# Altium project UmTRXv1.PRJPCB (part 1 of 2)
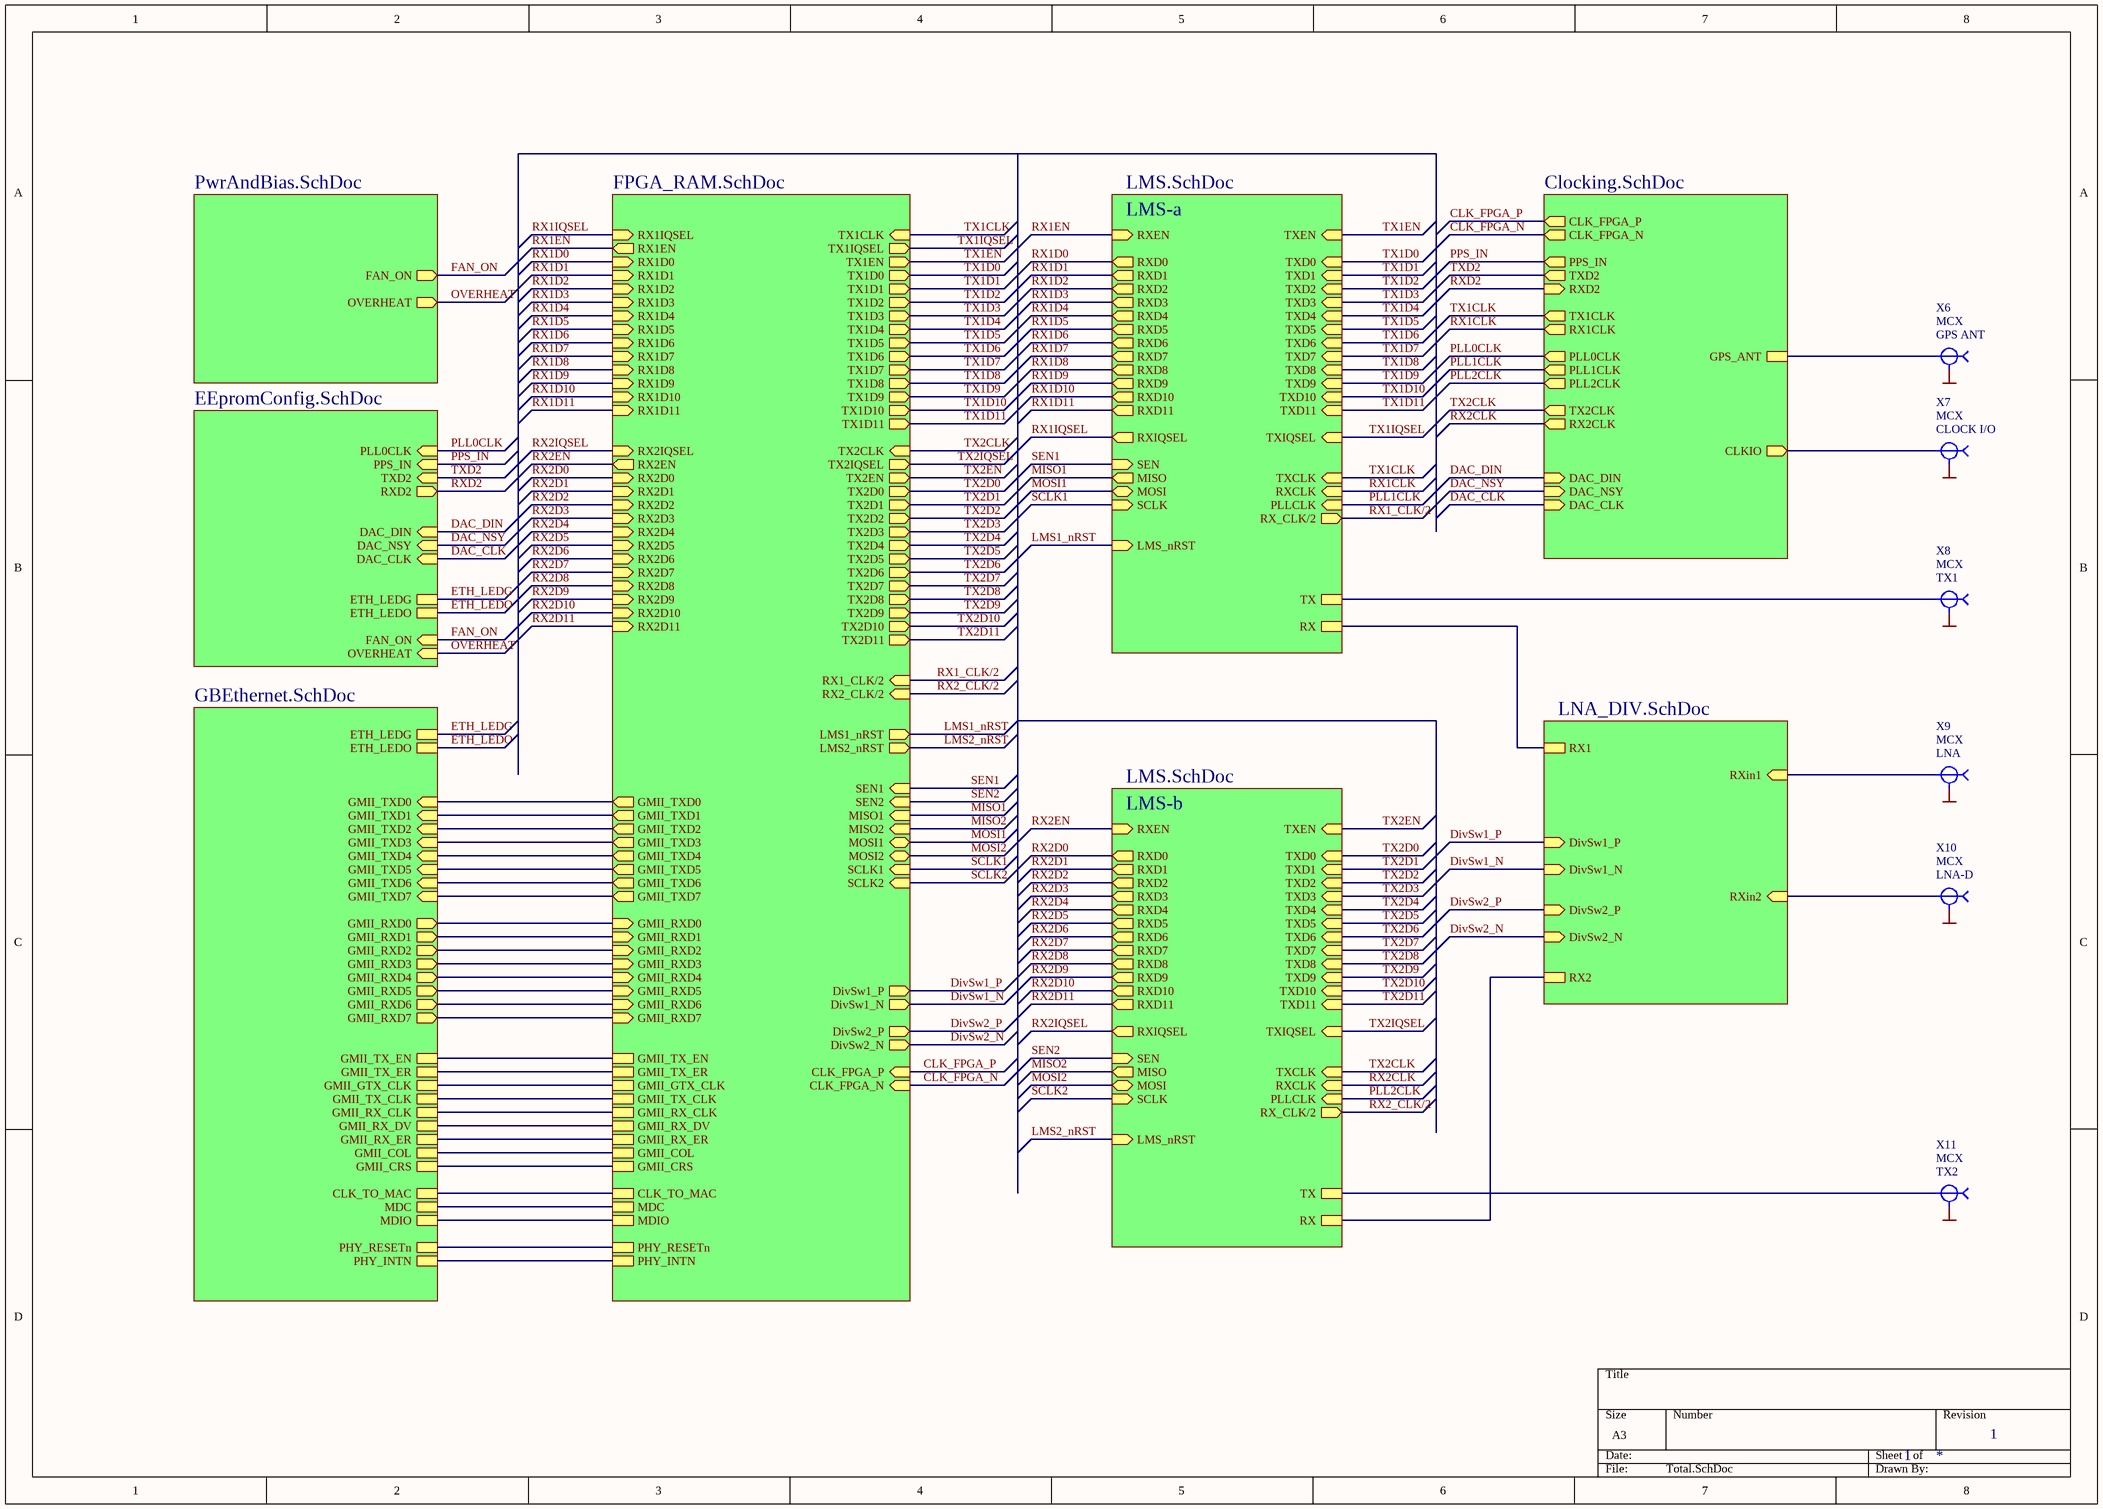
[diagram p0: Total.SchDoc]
8 sheets, 766 parts. Net scope: hierarchical (ports join the sheet entries above them; power ports are global).
Board file: UmTRXv1.PcbDoc
Sheets:
  Total.SchDoc
    PwrAndBias = PwrAndBias.SchDoc
    FPGA_RAM = FPGA_RAM.SchDoc
    GBEthernet = GBEthernet.SchDoc
    EEpromConfig = EEpromConfig.SchDoc
    Clocking = Clocking.SchDoc
    LMS-a = LMS.SchDoc
    LNA_DIV = LNA_DIV.SchDoc
    LMS-b = LMS.SchDoc

## Sheet Total.SchDoc: USRP Cellular Tranceiver
size A3; Revision: 1; SheetNumber: 1

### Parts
X6  MCX  Dscription: GPS ANT  [RF-MCX]
X7  MCX  Dscription: CLOCK I/O  [RF-MCX]
X8  MCX  Dscription: TX1  [RF-MCX]
X9  MCX  Dscription: LNA  [RF-MCX]
X10  MCX  Dscription: LNA-D  [RF-MCX]
X11  MCX  Dscription: TX2  [RF-MCX]

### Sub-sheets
Clocking = Clocking.SchDoc: RXD2 (in), RX2CLK (out), TX2CLK (out), CLKIO (out), CLK_FPGA_P (out), CLK_FPGA_N (out), RX1CLK (out), PLL1CLK (out), TX1CLK (out), GPS_ANT, DAC_DIN (in), DAC_NSY (in), DAC_CLK (in), PPS_IN (out), TXD2 (out), PLL2CLK (out), PLL0CLK (out)
EEpromConfig = EEpromConfig.SchDoc: PPS_IN (in), DAC_DIN (in), DAC_NSY (in), DAC_CLK (in), RXD2 (out), TXD2 (in), ETH_LEDG, ETH_LEDO, PLL0CLK (in), FAN_ON (in), OVERHEAT (in)
FPGA_RAM = FPGA_RAM.SchDoc: DivSw1_P (out), DivSw1_N (out), TX1IQSEL (out), TX2IQSEL (out), RX1IQSEL (in), RX2IQSEL (in), SEN1 (in), SEN2 (in), MISO1 (in), MOSI1 (bidir), SCLK1 (in), RX1EN (out), TX1EN (out), DivSw2_P (out), DivSw2_N (out), CLK_FPGA_P (in), CLK_FPGA_N (in), CLK_TO_MAC, GMII_TX_EN, GMII_TX_ER, GMII_GTX_CLK, GMII_TX_CLK, GMII_RX_CLK, GMII_RX_DV, GMII_RX_ER, GMII_COL, GMII_CRS, MDIO, MDC, PHY_INTN, PHY_RESETn, MISO2 (in), MOSI2 (bidir), SCLK2 (in), LMS1_nRST (out), RX1_CLK/2 (in), RX2_CLK/2 (in), TX2EN (out), RX2EN (out), LMS2_nRST (out), TX2CLK (in), TX1CLK (in), TX1D0 (out), TX1D1 (out), TX1D2 (out), TX1D3 (out), TX1D4 (out), TX1D5 (out), TX1D6 (out), TX1D7 (out), TX1D8 (out), TX1D9 (out), TX1D10 (out), TX1D11 (out), TX2D0 (out), TX2D1 (out), TX2D2 (out), TX2D3 (out), TX2D4 (out), TX2D5 (out), TX2D6 (out), TX2D7 (out), TX2D8 (out), TX2D9 (out), TX2D10 (out), TX2D11 (out), RX1D0 (in), RX1D1 (in), RX1D2 (in), RX1D3 (in), RX1D4 (in), RX1D5 (in), RX1D6 (in), RX1D7 (in), RX1D8 (in), RX1D9 (in), RX1D10 (in), RX1D11 (in), RX2D0 (in), RX2D1 (in), RX2D2 (in), RX2D3 (in), RX2D4 (in), RX2D5 (in), RX2D6 (in), RX2D7 (in), RX2D8 (in), RX2D9 (in), RX2D10 (in), RX2D11 (in), GMII_TXD0 (out), GMII_TXD1 (out), GMII_TXD2 (out), GMII_TXD3 (out), GMII_TXD4 (out), GMII_TXD5 (out), GMII_TXD6 (out), GMII_TXD7 (out), GMII_RXD0 (in), GMII_RXD1 (in), GMII_RXD2 (in), GMII_RXD3 (in), GMII_RXD4 (in), GMII_RXD5 (in), GMII_RXD6 (in), GMII_RXD7 (in)
GBEthernet = GBEthernet.SchDoc: CLK_TO_MAC, GMII_TX_ER, GMII_TX_EN, GMII_GTX_CLK, GMII_RX_CLK, GMII_TX_CLK, GMII_RX_DV, GMII_RX_ER, GMII_COL, GMII_CRS, MDC, MDIO, PHY_INTN, PHY_RESETn, ETH_LEDG, GMII_TXD0 (in), GMII_TXD1 (in), GMII_TXD2 (in), GMII_TXD3 (in), GMII_TXD4 (in), GMII_TXD5 (in), GMII_TXD6 (in), GMII_TXD7 (in), GMII_RXD0 (out), GMII_RXD1 (out), GMII_RXD2 (out), GMII_RXD3 (out), GMII_RXD4 (out), GMII_RXD5 (out), GMII_RXD6 (out), GMII_RXD7 (out), ETH_LEDO
LMS-a = LMS.SchDoc: RXD0 (out), RXIQSEL (out), SEN (in), MISO (out), MOSI (bidir), SCLK (in), RXD1 (out), RXD2 (out), RXD3 (out), RXD4 (out), RXD5 (out), RXD6 (out), RXD7 (out), RXD8 (out), RXD9 (out), RXD10 (out), RXD11 (out), RXEN (in), TXD0 (in), TXIQSEL (in), PLLCLK (in), RXCLK (in), TXCLK (in), TXD1 (in), TXD2 (in), TXD3 (in), TXD4 (in), TXD5 (in), TXD6 (in), TXD7 (in), TXD8 (in), TXD9 (in), TXD10 (in), TXD11 (in), TXEN (in), TX, RX, LMS_nRST (in), RX_CLK/2 (out)
LMS-b = LMS.SchDoc: RXD0 (out), RXIQSEL (out), SEN (in), MISO (out), MOSI (bidir), SCLK (in), RXD1 (out), RXD2 (out), RXD3 (out), RXD4 (out), RXD5 (out), RXD6 (out), RXD7 (out), RXD8 (out), RXD9 (out), RXD10 (out), RXD11 (out), RXEN (in), TXD0 (in), TXIQSEL (in), PLLCLK (in), RXCLK (in), TXCLK (in), TXD1 (in), TXD2 (in), TXD3 (in), TXD4 (in), TXD5 (in), TXD6 (in), TXD7 (in), TXD8 (in), TXD9 (in), TXD10 (in), TXD11 (in), TXEN (in), TX, RX, LMS_nRST (in), RX_CLK/2 (out)
LNA_DIV = LNA_DIV.SchDoc: RX1, RX2, RXin1 (in), RXin2 (in), DivSw1_P (in), DivSw1_N (in), DivSw2_P (in), DivSw2_N (in)
PwrAndBias = PwrAndBias.SchDoc: FAN_ON (out), OVERHEAT (out)

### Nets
GND: X6.2(GND) X7.2(GND) X8.2(GND) X9.2(GND) X10.2(GND) X11.2(GND)
CLK_FPGA_N: sheet FPGA_RAM/CLK_FPGA_N, sheet Clocking/CLK_FPGA_N
CLK_FPGA_P: sheet FPGA_RAM/CLK_FPGA_P, sheet Clocking/CLK_FPGA_P
CLK_TO_MAC: sheet FPGA_RAM/CLK_TO_MAC, sheet GBEthernet/CLK_TO_MAC
CLKIO: X7.1 ; sheet Clocking/CLKIO
DAC_CLK: sheet EEpromConfig/DAC_CLK, sheet Clocking/DAC_CLK
DAC_DIN: sheet EEpromConfig/DAC_DIN, sheet Clocking/DAC_DIN
DAC_NSY: sheet EEpromConfig/DAC_NSY, sheet Clocking/DAC_NSY
DivSw1_N: sheet FPGA_RAM/DivSw1_N, sheet LNA_DIV/DivSw1_N
DivSw1_P: sheet FPGA_RAM/DivSw1_P, sheet LNA_DIV/DivSw1_P
DivSw2_N: sheet FPGA_RAM/DivSw2_N, sheet LNA_DIV/DivSw2_N
DivSw2_P: sheet FPGA_RAM/DivSw2_P, sheet LNA_DIV/DivSw2_P
ETH_LEDG: sheet GBEthernet/ETH_LEDG, sheet EEpromConfig/ETH_LEDG
ETH_LEDO: sheet GBEthernet/ETH_LEDO, sheet EEpromConfig/ETH_LEDO
FAN_ON: sheet PwrAndBias/FAN_ON, sheet EEpromConfig/FAN_ON
GMII_COL: sheet FPGA_RAM/GMII_COL, sheet GBEthernet/GMII_COL
GMII_CRS: sheet FPGA_RAM/GMII_CRS, sheet GBEthernet/GMII_CRS
GMII_GTX_CLK: sheet FPGA_RAM/GMII_GTX_CLK, sheet GBEthernet/GMII_GTX_CLK
GMII_RX_CLK: sheet FPGA_RAM/GMII_RX_CLK, sheet GBEthernet/GMII_RX_CLK
GMII_RX_DV: sheet FPGA_RAM/GMII_RX_DV, sheet GBEthernet/GMII_RX_DV
GMII_RX_ER: sheet FPGA_RAM/GMII_RX_ER, sheet GBEthernet/GMII_RX_ER
GMII_RXD0: sheet FPGA_RAM/GMII_RXD0, sheet GBEthernet/GMII_RXD0
GMII_RXD1: sheet FPGA_RAM/GMII_RXD1, sheet GBEthernet/GMII_RXD1
GMII_RXD2: sheet FPGA_RAM/GMII_RXD2, sheet GBEthernet/GMII_RXD2
GMII_RXD3: sheet FPGA_RAM/GMII_RXD3, sheet GBEthernet/GMII_RXD3
GMII_RXD4: sheet FPGA_RAM/GMII_RXD4, sheet GBEthernet/GMII_RXD4
GMII_RXD5: sheet FPGA_RAM/GMII_RXD5, sheet GBEthernet/GMII_RXD5
GMII_RXD6: sheet FPGA_RAM/GMII_RXD6, sheet GBEthernet/GMII_RXD6
GMII_RXD7: sheet FPGA_RAM/GMII_RXD7, sheet GBEthernet/GMII_RXD7
GMII_TX_CLK: sheet FPGA_RAM/GMII_TX_CLK, sheet GBEthernet/GMII_TX_CLK
GMII_TX_EN: sheet FPGA_RAM/GMII_TX_EN, sheet GBEthernet/GMII_TX_EN
GMII_TX_ER: sheet FPGA_RAM/GMII_TX_ER, sheet GBEthernet/GMII_TX_ER
GMII_TXD0: sheet FPGA_RAM/GMII_TXD0, sheet GBEthernet/GMII_TXD0
GMII_TXD1: sheet FPGA_RAM/GMII_TXD1, sheet GBEthernet/GMII_TXD1
GMII_TXD2: sheet FPGA_RAM/GMII_TXD2, sheet GBEthernet/GMII_TXD2
GMII_TXD3: sheet FPGA_RAM/GMII_TXD3, sheet GBEthernet/GMII_TXD3
GMII_TXD4: sheet FPGA_RAM/GMII_TXD4, sheet GBEthernet/GMII_TXD4
GMII_TXD5: sheet FPGA_RAM/GMII_TXD5, sheet GBEthernet/GMII_TXD5
GMII_TXD6: sheet FPGA_RAM/GMII_TXD6, sheet GBEthernet/GMII_TXD6
GMII_TXD7: sheet FPGA_RAM/GMII_TXD7, sheet GBEthernet/GMII_TXD7
GPS_ANT: X6.1 ; sheet Clocking/GPS_ANT
LMS1_nRST: sheet FPGA_RAM/LMS1_nRST, sheet LMS-a/LMS_nRST
LMS2_nRST: sheet FPGA_RAM/LMS2_nRST, sheet LMS-b/LMS_nRST
MDC: sheet FPGA_RAM/MDC, sheet GBEthernet/MDC
MDIO: sheet FPGA_RAM/MDIO, sheet GBEthernet/MDIO
MISO1: sheet FPGA_RAM/MISO1, sheet LMS-a/MISO
MISO2: sheet FPGA_RAM/MISO2, sheet LMS-b/MISO
MOSI1: sheet FPGA_RAM/MOSI1, sheet LMS-a/MOSI
MOSI2: sheet FPGA_RAM/MOSI2, sheet LMS-b/MOSI
OVERHEAT: sheet PwrAndBias/OVERHEAT, sheet EEpromConfig/OVERHEAT
PHY_INTN: sheet FPGA_RAM/PHY_INTN, sheet GBEthernet/PHY_INTN
PHY_RESETn: sheet FPGA_RAM/PHY_RESETn, sheet GBEthernet/PHY_RESETn
PLL0CLK: sheet EEpromConfig/PLL0CLK, sheet Clocking/PLL0CLK
PLL1CLK: sheet Clocking/PLL1CLK, sheet LMS-a/PLLCLK
PLL2CLK: sheet Clocking/PLL2CLK, sheet LMS-b/PLLCLK
PPS_IN: sheet EEpromConfig/PPS_IN, sheet Clocking/PPS_IN
RX: sheet LMS-a/RX, sheet LNA_DIV/RX1
RX: sheet LNA_DIV/RX2, sheet LMS-b/RX  [a separate net that carries the same name]
RX1_CLK/2: sheet FPGA_RAM/RX1_CLK/2, sheet LMS-a/RX_CLK/2
RX1CLK: sheet Clocking/RX1CLK, sheet LMS-a/RXCLK
RX1D0: sheet FPGA_RAM/RX1D0, sheet LMS-a/RXD0
RX1D1: sheet FPGA_RAM/RX1D1, sheet LMS-a/RXD1
RX1D2: sheet FPGA_RAM/RX1D2, sheet LMS-a/RXD2
RX1D3: sheet FPGA_RAM/RX1D3, sheet LMS-a/RXD3
RX1D4: sheet FPGA_RAM/RX1D4, sheet LMS-a/RXD4
RX1D5: sheet FPGA_RAM/RX1D5, sheet LMS-a/RXD5
RX1D6: sheet FPGA_RAM/RX1D6, sheet LMS-a/RXD6
RX1D7: sheet FPGA_RAM/RX1D7, sheet LMS-a/RXD7
RX1D8: sheet FPGA_RAM/RX1D8, sheet LMS-a/RXD8
RX1D9: sheet FPGA_RAM/RX1D9, sheet LMS-a/RXD9
RX1D10: sheet FPGA_RAM/RX1D10, sheet LMS-a/RXD10
RX1D11: sheet FPGA_RAM/RX1D11, sheet LMS-a/RXD11
RX1EN: sheet FPGA_RAM/RX1EN, sheet LMS-a/RXEN
RX1IQSEL: sheet FPGA_RAM/RX1IQSEL, sheet LMS-a/RXIQSEL
RX2_CLK/2: sheet FPGA_RAM/RX2_CLK/2, sheet LMS-b/RX_CLK/2
RX2CLK: sheet Clocking/RX2CLK, sheet LMS-b/RXCLK
RX2D0: sheet FPGA_RAM/RX2D0, sheet LMS-b/RXD0
RX2D1: sheet FPGA_RAM/RX2D1, sheet LMS-b/RXD1
RX2D2: sheet FPGA_RAM/RX2D2, sheet LMS-b/RXD2
RX2D3: sheet FPGA_RAM/RX2D3, sheet LMS-b/RXD3
RX2D4: sheet FPGA_RAM/RX2D4, sheet LMS-b/RXD4
RX2D5: sheet FPGA_RAM/RX2D5, sheet LMS-b/RXD5
RX2D6: sheet FPGA_RAM/RX2D6, sheet LMS-b/RXD6
RX2D7: sheet FPGA_RAM/RX2D7, sheet LMS-b/RXD7
RX2D8: sheet FPGA_RAM/RX2D8, sheet LMS-b/RXD8
RX2D9: sheet FPGA_RAM/RX2D9, sheet LMS-b/RXD9
RX2D10: sheet FPGA_RAM/RX2D10, sheet LMS-b/RXD10
RX2D11: sheet FPGA_RAM/RX2D11, sheet LMS-b/RXD11
RX2EN: sheet FPGA_RAM/RX2EN, sheet LMS-b/RXEN
RX2IQSEL: sheet FPGA_RAM/RX2IQSEL, sheet LMS-b/RXIQSEL
RXD2: sheet EEpromConfig/RXD2, sheet Clocking/RXD2
RXin1: X9.1 ; sheet LNA_DIV/RXin1
RXin2: X10.1 ; sheet LNA_DIV/RXin2
SCLK1: sheet FPGA_RAM/SCLK1, sheet LMS-a/SCLK
SCLK2: sheet FPGA_RAM/SCLK2, sheet LMS-b/SCLK
SEN1: sheet FPGA_RAM/SEN1, sheet LMS-a/SEN
SEN2: sheet FPGA_RAM/SEN2, sheet LMS-b/SEN
TX: X8.1 ; sheet LMS-a/TX
TX: X11.1 ; sheet LMS-b/TX  [a separate net that carries the same name]
TX1CLK: sheet FPGA_RAM/TX1CLK, sheet Clocking/TX1CLK, sheet LMS-a/TXCLK
TX1D0: sheet FPGA_RAM/TX1D0, sheet LMS-a/TXD0
TX1D1: sheet FPGA_RAM/TX1D1, sheet LMS-a/TXD1
TX1D2: sheet FPGA_RAM/TX1D2, sheet LMS-a/TXD2
TX1D3: sheet FPGA_RAM/TX1D3, sheet LMS-a/TXD3
TX1D4: sheet FPGA_RAM/TX1D4, sheet LMS-a/TXD4
TX1D5: sheet FPGA_RAM/TX1D5, sheet LMS-a/TXD5
TX1D6: sheet FPGA_RAM/TX1D6, sheet LMS-a/TXD6
TX1D7: sheet FPGA_RAM/TX1D7, sheet LMS-a/TXD7
TX1D8: sheet FPGA_RAM/TX1D8, sheet LMS-a/TXD8
TX1D9: sheet FPGA_RAM/TX1D9, sheet LMS-a/TXD9
TX1D10: sheet FPGA_RAM/TX1D10, sheet LMS-a/TXD10
TX1D11: sheet FPGA_RAM/TX1D11, sheet LMS-a/TXD11
TX1EN: sheet FPGA_RAM/TX1EN, sheet LMS-a/TXEN
TX1IQSEL: sheet FPGA_RAM/TX1IQSEL, sheet LMS-a/TXIQSEL
TX2CLK: sheet FPGA_RAM/TX2CLK, sheet Clocking/TX2CLK, sheet LMS-b/TXCLK
TX2D0: sheet FPGA_RAM/TX2D0, sheet LMS-b/TXD0
TX2D1: sheet FPGA_RAM/TX2D1, sheet LMS-b/TXD1
TX2D2: sheet FPGA_RAM/TX2D2, sheet LMS-b/TXD2
TX2D3: sheet FPGA_RAM/TX2D3, sheet LMS-b/TXD3
TX2D4: sheet FPGA_RAM/TX2D4, sheet LMS-b/TXD4
TX2D5: sheet FPGA_RAM/TX2D5, sheet LMS-b/TXD5
TX2D6: sheet FPGA_RAM/TX2D6, sheet LMS-b/TXD6
TX2D7: sheet FPGA_RAM/TX2D7, sheet LMS-b/TXD7
TX2D8: sheet FPGA_RAM/TX2D8, sheet LMS-b/TXD8
TX2D9: sheet FPGA_RAM/TX2D9, sheet LMS-b/TXD9
TX2D10: sheet FPGA_RAM/TX2D10, sheet LMS-b/TXD10
TX2D11: sheet FPGA_RAM/TX2D11, sheet LMS-b/TXD11
TX2EN: sheet FPGA_RAM/TX2EN, sheet LMS-b/TXEN
TX2IQSEL: sheet FPGA_RAM/TX2IQSEL, sheet LMS-b/TXIQSEL
TXD2: sheet EEpromConfig/TXD2, sheet Clocking/TXD2

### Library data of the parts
X6-X11 = MCX SM

## Sheet PwrAndBias.SchDoc: Pwr And Biasing
size A3; Revision: 1; SheetNumber: 9
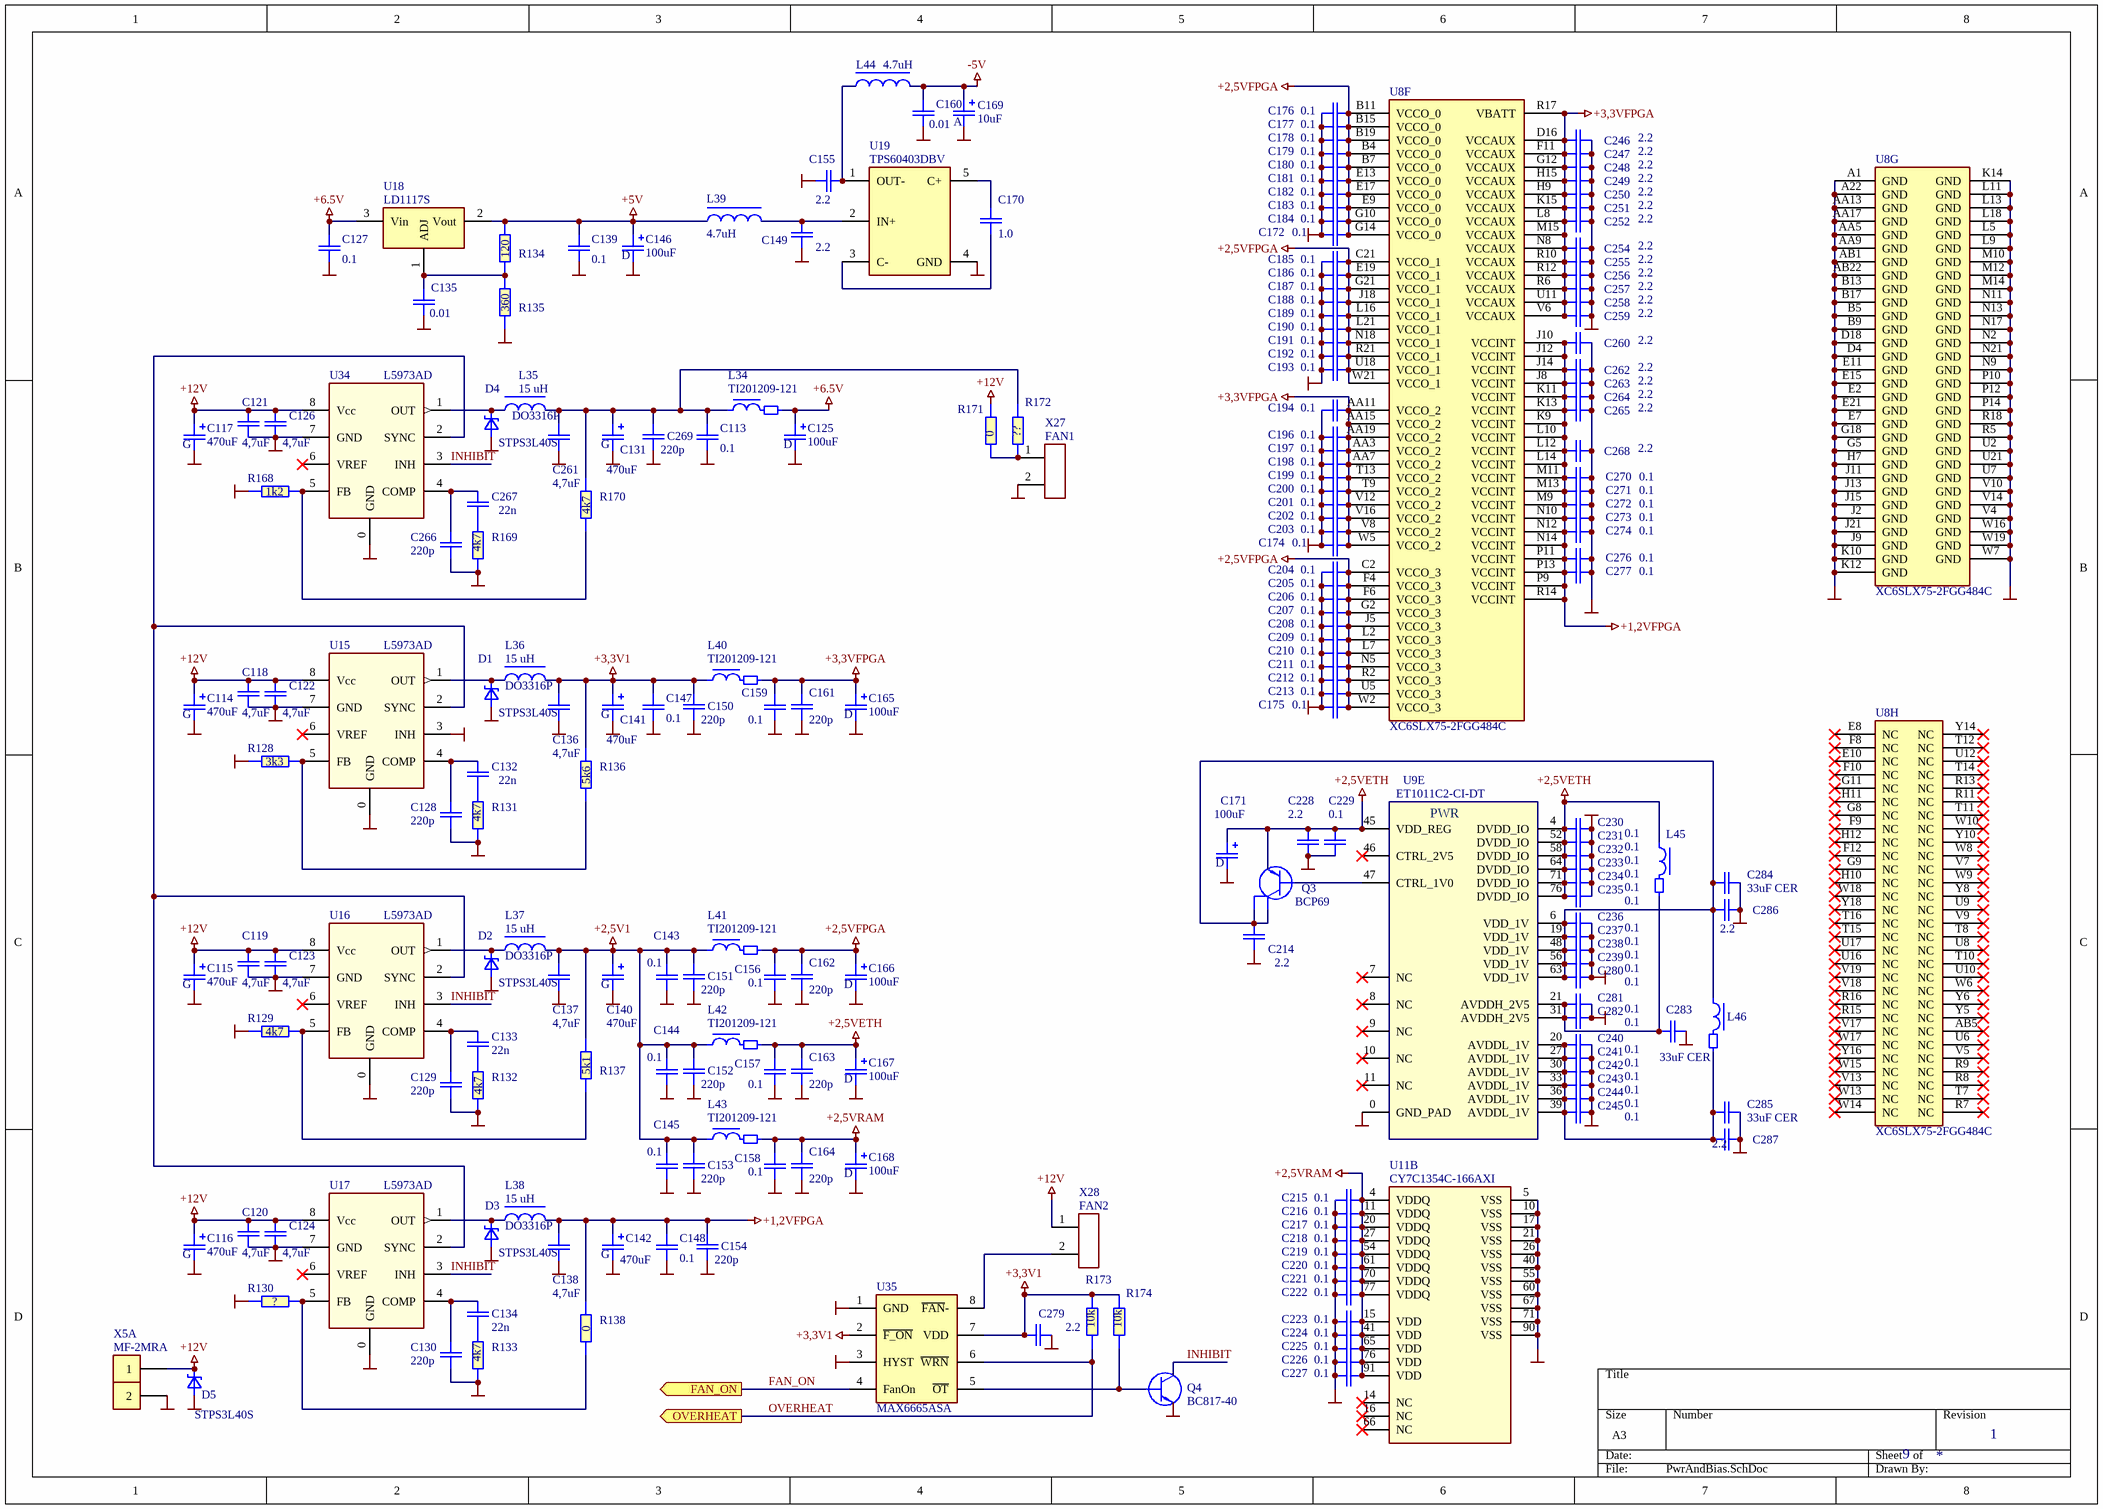
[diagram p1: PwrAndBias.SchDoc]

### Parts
C113  0.1  [C0402-Phillips]
C114  470uF  [CASE-G]
C115  470uF  [CASE-G]
C116  470uF  [CASE-G]
C117  470uF  [CASE-G]
C118  4,7uF  [c1206]
C119  4,7uF  [c1206]
C120  4,7uF  [c1206]
C121  4,7uF  [c1206]
C122  4,7uF  [c1206]
C123  4,7uF  [c1206]
C124  4,7uF  [c1206]
C125  100uF  [cd7343]
C126  4,7uF  [c1206]
C127  0.1  [C0402-Phillips]
C128  220p  [C0603-PHILLIPS]
C129  220p  [C0603-PHILLIPS]
C130  220p  [C0603-PHILLIPS]
C131  470uF  [CASE-G]
C132  22n  [C0603-PHILLIPS]
C133  22n  [C0603-PHILLIPS]
C134  22n  [C0603-PHILLIPS]
C135  0.01  [C0402-Phillips]
C136  4,7uF  [c1206]
C137  4,7uF  [c1206]
C138  4,7uF  [c1206]
C139  0.1  [C0402-Phillips]
C140  470uF  [CASE-G]
C141  470uF  [CASE-G]
C142  470uF  [CASE-G]
C143  0.1  [C0402-Phillips]
C144  0.1  [C0402-Phillips]
C145  0.1  [C0402-Phillips]
C146  100uF  [cd7343]
C147  0.1  [C0402-Phillips]
C148  0.1  [C0402-Phillips]
C149  2.2  [C0402-Phillips]
C150  220p  [C0603-PHILLIPS]
C151  220p  [C0603-PHILLIPS]
C152  220p  [C0603-PHILLIPS]
C153  220p  [C0603-PHILLIPS]
C154  220p  [C0603-PHILLIPS]
C155  2.2  [C0402-Phillips]
C156  0.1  [C0402-Phillips]
C157  0.1  [C0402-Phillips]
C158  0.1  [C0402-Phillips]
C159  0.1  [C0402-Phillips]
C160  0.01  [C0402-Phillips]
C161  220p  [C0603-PHILLIPS]
C162  220p  [C0603-PHILLIPS]
C163  220p  [C0603-PHILLIPS]
C164  220p  [C0603-PHILLIPS]
C165  100uF  [cd7343]
C166  100uF  [cd7343]
C167  100uF  [cd7343]
C168  100uF  [cd7343]
C169  10uF  [CA3216]
C170  1.0  [C0603-PHILLIPS]
C171  100uF  [cd7343]
C172  0.1  [C0402-cirq]
C174  0.1  [C0402-cirq]
C175  0.1  [C0402-cirq]
C176  0.1  [C0402-cirq]
C177  0.1  [C0402-cirq]
C178  0.1  [C0402-cirq]
C179  0.1  [C0402-cirq]
C180  0.1  [C0402-cirq]
C181  0.1  [C0402-cirq]
C182  0.1  [C0402-cirq]
C183  0.1  [C0402-cirq]
C184  0.1  [C0402-cirq]
C185  0.1  [C0402-cirq]
C186  0.1  [C0402-cirq]
C187  0.1  [C0402-cirq]
C188  0.1  [C0402-cirq]
C189  0.1  [C0402-cirq]
C190  0.1  [C0402-cirq]
C191  0.1  [C0402-cirq]
C192  0.1  [C0402-cirq]
C193  0.1  [C0402-cirq]
C194  0.1  [C0402-cirq]
C196  0.1  [C0402-cirq]
C197  0.1  [C0402-cirq]
C198  0.1  [C0402-cirq]
C199  0.1  [C0402-cirq]
C200  0.1  [C0402-cirq]
C201  0.1  [C0402-cirq]
C202  0.1  [C0402-cirq]
C203  0.1  [C0402-cirq]
C204  0.1  [C0402-cirq]
C205  0.1  [C0402-cirq]
C206  0.1  [C0402-cirq]
C207  0.1  [C0402-cirq]
C208  0.1  [C0402-cirq]
C209  0.1  [C0402-cirq]
C210  0.1  [C0402-cirq]
C211  0.1  [C0402-cirq]
C212  0.1  [C0402-cirq]
C213  0.1  [C0402-cirq]
C214  2.2  [C0402-Phillips]
C215  0.1  [C0402-Phillips]
C216  0.1  [C0402-Phillips]
C217  0.1  [C0402-Phillips]
C218  0.1  [C0402-Phillips]
C219  0.1  [C0402-Phillips]
C220  0.1  [C0402-Phillips]
C221  0.1  [C0402-Phillips]
C222  0.1  [C0402-Phillips]
C223  0.1  [C0402-Phillips]
C224  0.1  [C0402-Phillips]
C225  0.1  [C0402-Phillips]
C226  0.1  [C0402-Phillips]
C227  0.1  [C0402-Phillips]
C228  2.2  [C0402-Phillips]
C229  0.1  [C0402-Phillips]
C230  0.1  [C0402-Phillips]
C231  0.1  [C0402-Phillips]
C232  0.1  [C0402-Phillips]
C233  0.1  [C0402-Phillips]
C234  0.1  [C0402-Phillips]
C235  0.1  [C0402-Phillips]
C236  0.1  [C0402-Phillips]
C237  0.1  [C0402-Phillips]
C238  0.1  [C0402-Phillips]
C239  0.1  [C0402-Phillips]
C240  0.1  [C0402-Phillips]
C241  0.1  [C0402-Phillips]
C242  0.1  [C0402-Phillips]
C243  0.1  [C0402-Phillips]
C244  0.1  [C0402-Phillips]
C245  0.1  [C0402-Phillips]
C246  2.2  [C0402-cirq]
C247  2.2  [C0402-cirq]
C248  2.2  [C0402-cirq]
C249  2.2  [C0402-cirq]
C250  2.2  [C0402-cirq]
C251  2.2  [C0402-cirq]
C252  2.2  [C0402-cirq]
C254  2.2  [C0402-cirq]
C255  2.2  [C0402-cirq]
C256  2.2  [C0402-cirq]
C257  2.2  [C0402-cirq]
C258  2.2  [C0402-cirq]
C259  2.2  [C0402-cirq]
C260  2.2  [C0402-cirq]
C261  4,7uF  [c1206]
C262  2.2  [C0402-cirq]
C263  2.2  [C0402-cirq]
C264  2.2  [C0402-cirq]
C265  2.2  [C0402-cirq]
C266  220p  [C0603-PHILLIPS]
C267  22n  [C0603-PHILLIPS]
C268  2.2  [C0402-cirq]
C269  220p  [C0603-PHILLIPS]
C270  0.1  [C0402-cirq]
C271  0.1  [C0402-cirq]
C272  0.1  [C0402-cirq]
C273  0.1  [C0402-cirq]
C274  0.1  [C0402-cirq]
C276  0.1  [C0402-cirq]
C277  0.1  [C0402-cirq]
C279  2.2  [C0402-Phillips]
C280  0.1  [C0402-Phillips]
C281  0.1  [C0402-Phillips]
C282  0.1  [C0402-Phillips]
C283  33uF CER  [C0805-Phillips]
C284  33uF CER  [C0805-Phillips]
C285  33uF CER  [C0805-Phillips]
C286  2.2  [C0402-Phillips]
C287  2.2  [C0402-Phillips]
D1  STPS3L40S  [SMC]
D2  STPS3L40S  [SMC]
D3  STPS3L40S  [SMC]
D4  STPS3L40S  [SMC]
D5  STPS3L40S  [SMC]
L34  TI201209-121  [TI2012-Phillips]
L35  15 uH  Name: DO3316P  [DS3316]
L36  15 uH  Name: DO3316P  [DS3316]
L37  15 uH  Name: DO3316P  [DS3316]
L38  15 uH  Name: DO3316P  [DS3316]
L39  4.7uH  [CR1812]
L40  TI201209-121  [TI2012-Phillips]
L41  TI201209-121  [TI2012-Phillips]
L42  TI201209-121  [TI2012-Phillips]
L43  TI201209-121  [TI2012-Phillips]
L44  4.7uH  [CR1812]
L45  TI160808U601  [Ti160808-Phillips]  (value not drawn)
L46  TI160808U601  [Ti160808-Phillips]  (value not drawn)
Q3  BCP69  [SOT-223]
Q4  BC817-40  [SOT23-Philips]
R128  3k3  [R0603-PHILLIPS]
R129  4k7  [R0603-PHILLIPS]
R130  ?  [R0603-PHILLIPS]
R131  4k7  [R0603-PHILLIPS]
R132  4k7  [R0603-PHILLIPS]
R133  4k7  [R0603-PHILLIPS]
R134  120  [R0603-PHILLIPS]
R135  360  [R0603-PHILLIPS]
R136  5k6  [R0603-PHILLIPS]
R137  5k1  [R0603-PHILLIPS]
R138  0  [R0603-PHILLIPS]
R168  1k2  [R0603-PHILLIPS]
R169  4k7  [R0603-PHILLIPS]
R170  4k7  [R0603-PHILLIPS]
R171  0  [R0603-PHILLIPS]
R172  ??  [R0603-PHILLIPS]
R173  10k  [R0603-PHILLIPS]
R174  10k  [R0603-PHILLIPS]
U8  XC6SLX75-2FGG484C  [FBGA484]  (parts F,G,H of 8)
U9  ET1011C2-CI-DT  [QFN-84(10x10/0/4mm)with_pad]  (part E of 5)
U11  CY7C1354C-166AXI  [QFP-10020X14/0.65]]  (part B of 2)
U15  L5973AD  [SOIC8 - BackGND - 0.4mm dia]
U16  L5973AD  [SOIC8 - BackGND - 0.4mm dia]
U17  L5973AD  [SOIC8 - BackGND - 0.4mm dia]
U18  LD1117S  [SOT-223-1]
U19  TPS60403DBV  [SOT-23-5[3.1x1.8/0.95]]
U34  L5973AD  [SOIC8 - BackGND - 0.4mm dia]
U35  MAX6665ASA  [SO-8]
X5  MF-2MRA  [MF-2MRA]  (parts A,B of 2)
X27  FAN1  [WF-2]
X28  FAN2  [WF-2]

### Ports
FAN_ON (out), OVERHEAT (out)

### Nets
+1,2VFPGA: C138.1 C142.1(+) C148.1 C154.1 C260.1 C262.1 C263.1 C264.1 C265.1 C268.1 C270.1 C271.1 C272.1 C273.1 C274.1 C276.1 C277.1 L38.1 R138.1 U8.J8(VCCINT) U8.J10(VCCINT) U8.J12(VCCINT) U8.J14(VCCINT) U8.K9(VCCINT) U8.K11(VCCINT) U8.K13(VCCINT) U8.L10(VCCINT) U8.L12(VCCINT) U8.L14(VCCINT) U8.M9(VCCINT) U8.M11(VCCINT) U8.M13(VCCINT) U8.N10(VCCINT) U8.N12(VCCINT) U8.N14(VCCINT) U8.P9(VCCINT) U8.P11(VCCINT) U8.P13(VCCINT) U8.R14(VCCINT)
+2,5V1: C137.1 C140.1(+) C143.1 C144.1 C145.1 C151.1 C152.1 C153.1 L37.1 L41.1 L42.1 L43.1 R137.1
+2,5VETH: C157.1 C163.1 C167.1(+) C171.1(+) C228.2 C229.1 C230.1 C231.1 C232.1 C233.1 C234.1 C235.1 L42.2 L45.1 Q3.3(E) U9.4(DVDD_IO) U9.45(VDD_REG) U9.52(DVDD_IO) U9.58(DVDD_IO) U9.64(DVDD_IO) U9.71(DVDD_IO) U9.76(DVDD_IO)
+2,5VFPGA: C156.1 C162.1 C166.1(+) C172.2 C175.2 C176.2 C177.2 C178.2 C179.2 C180.2 C181.2 C182.2 C183.2 C184.2 C185.2 C186.2 C187.2 C188.2 C189.2 C190.2 C191.2 C192.2 C193.2 C204.2 C205.2 C206.2 C207.2 C208.2 C209.2 C210.2 C211.2 C212.2 C213.2 L41.2 U8.B4(VCCO_0) U8.B7(VCCO_0) U8.B11(VCCO_0) U8.B15(VCCO_0) U8.B19(VCCO_0) U8.C2(VCCO_3) U8.C21(VCCO_1) U8.E9(VCCO_0) U8.E13(VCCO_0) U8.E17(VCCO_0) U8.E19(VCCO_1) U8.F4(VCCO_3) U8.F6(VCCO_3) U8.G2(VCCO_3) U8.G10(VCCO_0) U8.G14(VCCO_0) U8.G21(VCCO_1) U8.J5(VCCO_3) U8.J18(VCCO_1) U8.L2(VCCO_3) U8.L7(VCCO_3) U8.L16(VCCO_1) U8.L21(VCCO_1) U8.N5(VCCO_3) U8.N18(VCCO_1) U8.R2(VCCO_3) U8.R21(VCCO_1) U8.U5(VCCO_3) U8.U18(VCCO_1) U8.W2(VCCO_3) U8.W21(VCCO_1)
+2,5VRAM: C158.1 C164.1 C168.1(+) C215.2 C216.2 C217.2 C218.2 C219.2 C220.2 C221.2 C222.2 C223.2 C224.2 C225.2 C226.2 C227.2 L43.2 U11.4(VDDQ) U11.11(VDDQ) U11.15(VDD) U11.20(VDDQ) U11.27(VDDQ) U11.41(VDD) U11.54(VDDQ) U11.61(VDDQ) U11.65(VDD) U11.70(VDDQ) U11.76(VDD) U11.77(VDDQ) U11.91(VDD)
+3,3V1: C136.1 C141.1(+) C147.1 C150.1 C279.1 L36.1 L40.1 R136.1 R173.1 R174.1 U35.2(~{F_ON}) U35.7(VDD)
+3,3VFPGA: C159.1 C161.1 C165.1(+) C174.2 C194.2 C196.2 C197.2 C198.2 C199.2 C200.2 C201.2 C202.2 C203.2 C246.1 C247.1 C248.1 C249.1 C250.1 C251.1 C252.1 C254.1 C255.1 C256.1 C257.1 C258.1 C259.1 L40.2 U8.AA3(VCCO_2) U8.AA7(VCCO_2) U8.AA11(VCCO_2) U8.AA15(VCCO_2) U8.AA19(VCCO_2) U8.D16(VCCAUX) U8.F11(VCCAUX) U8.G12(VCCAUX) U8.H9(VCCAUX) U8.H15(VCCAUX) U8.K15(VCCAUX) U8.L8(VCCAUX) U8.M15(VCCAUX) U8.N8(VCCAUX) U8.R6(VCCAUX) U8.R10(VCCAUX) U8.R12(VCCAUX) U8.R17(VBATT) U8.T9(VCCO_2) U8.T13(VCCO_2) U8.U11(VCCAUX) U8.V6(VCCAUX) U8.V8(VCCO_2) U8.V12(VCCO_2) U8.V16(VCCO_2) U8.W5(VCCO_2)
+5V: C139.1 C146.1(+) L39.1 R134.1 U18.2(Vout)
+6.5V: C125.1(+) C127.1 L34.2 U18.3(Vin)
+12V: C114.1(+) C115.1(+) C116.1(+) C117.1(+) C118.1 C119.1 C120.1 C121.1 C122.1 C123.1 C124.1 C126.1 D5.2(C) R171.1 U15.8(Vcc) U16.8(Vcc) U17.8(Vcc) U34.8(Vcc) X5.1 X28.1
-5V: C160.1 C169.1(+) L44.2
GND: C113.2 C114.2(-) C115.2(-) C116.2(-) C117.2(-) C118.2 C119.2 C120.2 C121.2 C122.2 C123.2 C124.2 C125.2(-) C126.2 C127.2 C128.2 C129.2 C130.2 C131.2(-) C135.2 C136.2 C137.2 C138.2 C139.2 C140.2(-) C141.2(-) C142.2(-) C143.2 C144.2 C145.2 C146.2(-) C147.2 C148.2 C149.1 C150.2 C151.2 C152.2 C153.2 C154.2 C155.2 C156.2 C157.2 C158.2 C159.2 C160.2 C161.2 C162.2 C163.2 C164.2 C165.2(-) C166.2(-) C167.2(-) C168.2(-) C169.2(-) C171.2(-) C172.1 C174.1 C175.1 C176.1 C177.1 C178.1 C179.1 C180.1 C181.1 C182.1 C183.1 C184.1 C185.1 C186.1 C187.1 C188.1 C189.1 C190.1 C191.1 C192.1 C193.1 C194.1 C196.1 C197.1 C198.1 C199.1 C200.1 C201.1 C202.1 C203.1 C204.1 C205.1 C206.1 C207.1 C208.1 C209.1 C210.1 C211.1 C212.1 C213.1 C214.1 C215.1 C216.1 C217.1 C218.1 C219.1 C220.1 C221.1 C222.1 C223.1 C224.1 C225.1 C226.1 C227.1 C228.1 C229.2 C230.2 C231.2 C232.2 C233.2 C234.2 C235.2 C236.2 C237.2 C238.2 C239.2 C240.2 C241.2 C242.2 C243.2 C244.2 C245.2 C246.2 C247.2 C248.2 C249.2 C250.2 C251.2 C252.2 C254.2 C255.2 C256.2 C257.2 C258.2 C259.2 C260.2 C261.2 C262.2 C263.2 C264.2 C265.2 C266.2 C268.2 C269.2 C270.2 C271.2 C272.2 C273.2 C274.2 C276.2 C277.2 C279.2 C280.2 C281.2 C282.2 C283.2 C284.2 C285.2 C286.1 C287.1 D1.1(A) D2.1(A) D3.1(A) D4.1(A) D5.1(A) Q4.2(E) R128.1 R129.1 R130.1 R131.2 R132.2 R133.2 R135.2 R168.1 R169.2 U8.A1(GND) U8.A22(GND) U8.AA5(GND) U8.AA9(GND) U8.AA13(GND) U8.AA17(GND) U8.AB1(GND) U8.AB22(GND) U8.B5(GND) U8.B9(GND) U8.B13(GND) U8.B17(GND) U8.D4(GND) U8.D18(GND) U8.E2(GND) U8.E7(GND) U8.E11(GND) U8.E15(GND) U8.E21(GND) U8.G5(GND) U8.G18(GND) U8.H7(GND) U8.J2(GND) U8.J9(GND) U8.J11(GND) U8.J13(GND) U8.J15(GND) U8.J21(GND) U8.K10(GND) U8.K12(GND) U8.K14(GND) U8.L5(GND) U8.L9(GND) U8.L11(GND) U8.L13(GND) U8.L18(GND) U8.M10(GND) U8.M12(GND) U8.M14(GND) U8.N2(GND) U8.N9(GND) U8.N11(GND) U8.N13(GND) U8.N17(GND) U8.N21(GND) U8.P10(GND) U8.P12(GND) U8.P14(GND) U8.R5(GND) U8.R18(GND) U8.U2(GND) U8.U7(GND) U8.U21(GND) U8.V4(GND) U8.V10(GND) U8.V14(GND) U8.W7(GND) U8.W16(GND) U8.W19(GND) U9.0(GND_PAD) U11.5(VSS) U11.10(VSS) U11.17(VSS) U11.21(VSS) U11.26(VSS) U11.40(VSS) U11.55(VSS) U11.60(VSS) U11.67(VSS) U11.71(VSS) U11.90(VSS) U15.0(GND) U15.3(INH) U15.7(GND) U16.0(GND) U16.7(GND) U17.0(GND) U17.7(GND) U19.4(GND) U34.0(GND) U34.7(GND) U35.1(GND) U35.3(HYST) X5.2 X27.2
FAN_ON: U35.4(FanOn) ; port FAN_ON
INHIBIT: Q4.3(C) U16.3(INH) U17.3(INH) U34.3(INH)
OVERHEAT: R173.2 U35.6(~{WRN}) ; port OVERHEAT
NetC113_1: C113.1 C131.1(+) C261.1 C269.1 L34.1 L35.1 R170.1 R172.1
NetC128_1: C128.1 C132.1 U15.4(COMP)
NetC129_1: C129.1 C133.1 U16.4(COMP)
NetC130_1: C130.1 C134.1 U17.4(COMP)
NetC132_2: C132.2 R131.1
NetC133_2: C133.2 R132.1
NetC134_2: C134.2 R133.1
NetC135_1: C135.1 R134.2 R135.1 U18.1(ADJ)
NetC149_2: C149.2 L39.2 U19.2(IN+)
NetC155_1: C155.1 L44.1 U19.1(OUT-)
NetC170_1: C170.1 U19.5(C+)
NetC170_2: C170.2 U19.3(C-)
NetC214_2: C214.2 C236.1 C237.1 C238.1 C239.1 C280.1 C284.1 C286.2 L46.1 Q3.2(C) Q3.4(C) U9.6(VDD_1V) U9.19(VDD_1V) U9.48(VDD_1V) U9.56(VDD_1V) U9.63(VDD_1V)
NetC240_1: C240.1 C241.1 C242.1 C243.1 C244.1 C245.1 C285.1 C287.2 L46.2 U9.20(AVDDL_1V) U9.27(AVDDL_1V) U9.30(AVDDL_1V) U9.33(AVDDL_1V) U9.36(AVDDL_1V) U9.39(AVDDL_1V)
NetC266_1: C266.1 C267.1 U34.4(COMP)
NetC267_2: C267.2 R169.1
NetC281_1: C281.1 C282.1 C283.1 L45.2 U9.21(AVDDH_2V5) U9.31(AVDDH_2V5)
NetD1_2: D1.2(C) L36.2 U15.1(OUT)
NetD2_2: D2.2(C) L37.2 U16.1(OUT)
NetD3_2: D3.2(C) L38.2 U17.1(OUT)
NetD4_2: D4.2(C) L35.2 U34.1(OUT)
NetQ3_1: Q3.1(B) U9.47(CTRL_1V0)
NetQ4_1: Q4.1(B) R174.2 U35.5(~{OT})
NetR128_2: R128.2 R136.2 U15.5(FB)
NetR129_2: R129.2 R137.2 U16.5(FB)
NetR130_2: R130.2 R138.2 U17.5(FB)
NetR168_2: R168.2 R170.2 U34.5(FB)
NetR171_2: R171.2 R172.2 X27.1
NetU15_2: U15.2(SYNC) U16.2(SYNC) U17.2(SYNC) U34.2(SYNC)
NetU35_8: U35.8(~{FAN}-) X28.2

Not connected (* = marked no-connect by the designer): U8 AB5(NC)* E8(NC)* E10(NC)* F8(NC)* F9(NC)* F10(NC)* F12(NC)* G8(NC)* G9(NC)* G11(NC)* H10(NC)* H11(NC)* H12(NC)* R7(NC)* R8(NC)* R9(NC)* R11(NC)* R13(NC)* R15(NC)* R16(NC)* T7(NC)* T8(NC)* T10(NC)* T11(NC)* T12(NC)* T14(NC)* T15(NC)* T16(NC)* U6(NC)* U8(NC)* U9(NC)* U10(NC)* U12(NC)* U16(NC)* U17(NC)* V5(NC)* V7(NC)* V9(NC)* V13(NC)* V17(NC)* V18(NC)* V19(NC)* W6(NC)* W8(NC)* W9(NC)* W10(NC)* W13(NC)* W14(NC)* W15(NC)* W17(NC)* W18(NC)* Y5(NC)* Y6(NC)* Y8(NC)* Y10(NC)* Y14(NC)* Y16(NC)* Y18(NC)*; U9 7(NC)* 8(NC)* 9(NC)* 10(NC)* 11(NC)* 46(CTRL_2V5)*; U11 14(NC)* 16(NC)* 66(NC)*; U15 6(VREF)*; U16 6(VREF)*; U17 6(VREF)*; U34 6(VREF)*

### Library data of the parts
C113 C127 C135 C139 C143-C145 C147-C149 C155-C160 C172 C174-C194 C196-C252 C254-C260 C262-C265 C268 C270-C274 C276 C277 C279-C282 C286 C287 = C0402: Конденсатор; Manufacturer: MURATA; Tolerance: 20%; Name: SMD0402; U/P/TKE: Y5V
C114-C117 C131 C140-C142 = CASE-G: Конденсатор; Manufacturer: SPRAGUE; U/P/TKE: 25V
C118-C124 C126 C136-C138 C261 = C1206: Конденсатор; Manufacturer: MURATA; Tolerance: 20%; Name: SMD1206; U/P/TKE: Y5V
C125 C146 C165-C168 C171 = CD7343: Конденсатор; Manufacturer: SPRAGUE; Name: CASE-G; U/P/TKE: 16V
C128-C130 C150-C154 C161-C164 C266 C269 = C0603: Конденсатор; Manufacturer: MURATA; Tolerance: 20%; Name: SMD0603; U/P/TKE: NP0
C132-C134 C267 = C0603: Конденсатор; Manufacturer: MURATA; Tolerance: 20%; Name: SMD0603; U/P/TKE: X7R
C169 = CA3216: Конденсатор; Manufacturer: SPRAGUE; Name: Case A; U/P/TKE: 10V
C170 = C0603: Конденсатор; Manufacturer: MURATA; Tolerance: 20%; Name: SMD0603; U/P/TKE: Y5V
C283-C285 = C0805: Конденсатор; Manufacturer: MURATA; Tolerance: 20%; Name: SMD0805; U/P/TKE: Y5R
D1-D5 = STPS3L40S: Диод; Manufacturer: ST; First: NAVCC00; PDF: d:\Proj\Components\ST\stps3l40s.pdf; Misc: Power Schottky rectifier
L34 L40-L43 = TI2012_1: Дроссель ЭМС; Manufacturer: MURATA
L35-L38 = DS3316P: Дроссель; Manufacturer: Coilcraft; PDF: d:\Proj\Components\Coilcraft\ds3316.pdf
L39 L44 = L-1812: Индуктивность; Manufacturer: MURATA
L45 L46 = TI160808: Дроссель ЭМС; Manufacturer: MURATA
Q3 = BCP69: Транзистор; Manufacturer: INFINEON
Q4 = BC 817: Транзистор; Manufacturer: Philips
R128-R138 R168-R174 = R0603: Резистор; Manufacturer: YAGEO; Tolerance: 5%; Name: SMD0603; U/P/TKE: 0.1W
U8 = XC6SLX75-2FGG484C: Spartan-6 LX 1.2V FPGA, 270 User I/Os, 484-Ball Fine-Pitch BGA (1.0mm Pitch), Speed Grade 2, Commercial Grade, Pb-Free; Manufacturer: Xilinx
U9 = ET1011C2-CI-DT: Микросхема; Manufacturer: LSI; PDF: d:\Proj\Components\LSI\Si5330.pdf; Misc: Gigabit Ethernet Transceiver
U11 = CY7C1354C-166AXI: Микросхема; Manufacturer: Cypress; Misc: Pipelined SRAM with NoBL™ Architecture; PDF: d:\Proj\Components\Cypress\CY7C1354C_CY7C1356C2.pdf
U15-U17 U34 = L5973D: Микросхема; Manufacturer: ST; Misc: step down switching regulator; Swap: No; PDF: d:\Proj\Components\ST\L5973D(stepdown2,5A)_ST.pdf
U18 = LD1117ADJ: Микросхема; Manufacturer: STMicro; Swap: No
U19 = TPS6040x: Микросхема; Manufacturer: TI; Swap: No
U35 = MAX6665ASA: Микросхема; Manufacturer: Maxim; Swap: No; PDF: d:\Proj\Components\Maxim\MAX6665.pdf; Misc: Fan Controller/Driver
X5 = MF-2MRA: Разъем; Manufacturer: BM
X27 X28 = WF-2: Разъем; Manufacturer: BM

## Sheet FPGA_RAM.SchDoc: BaseBand Front-End
size A2; Revision: 1; SheetNumber: 2
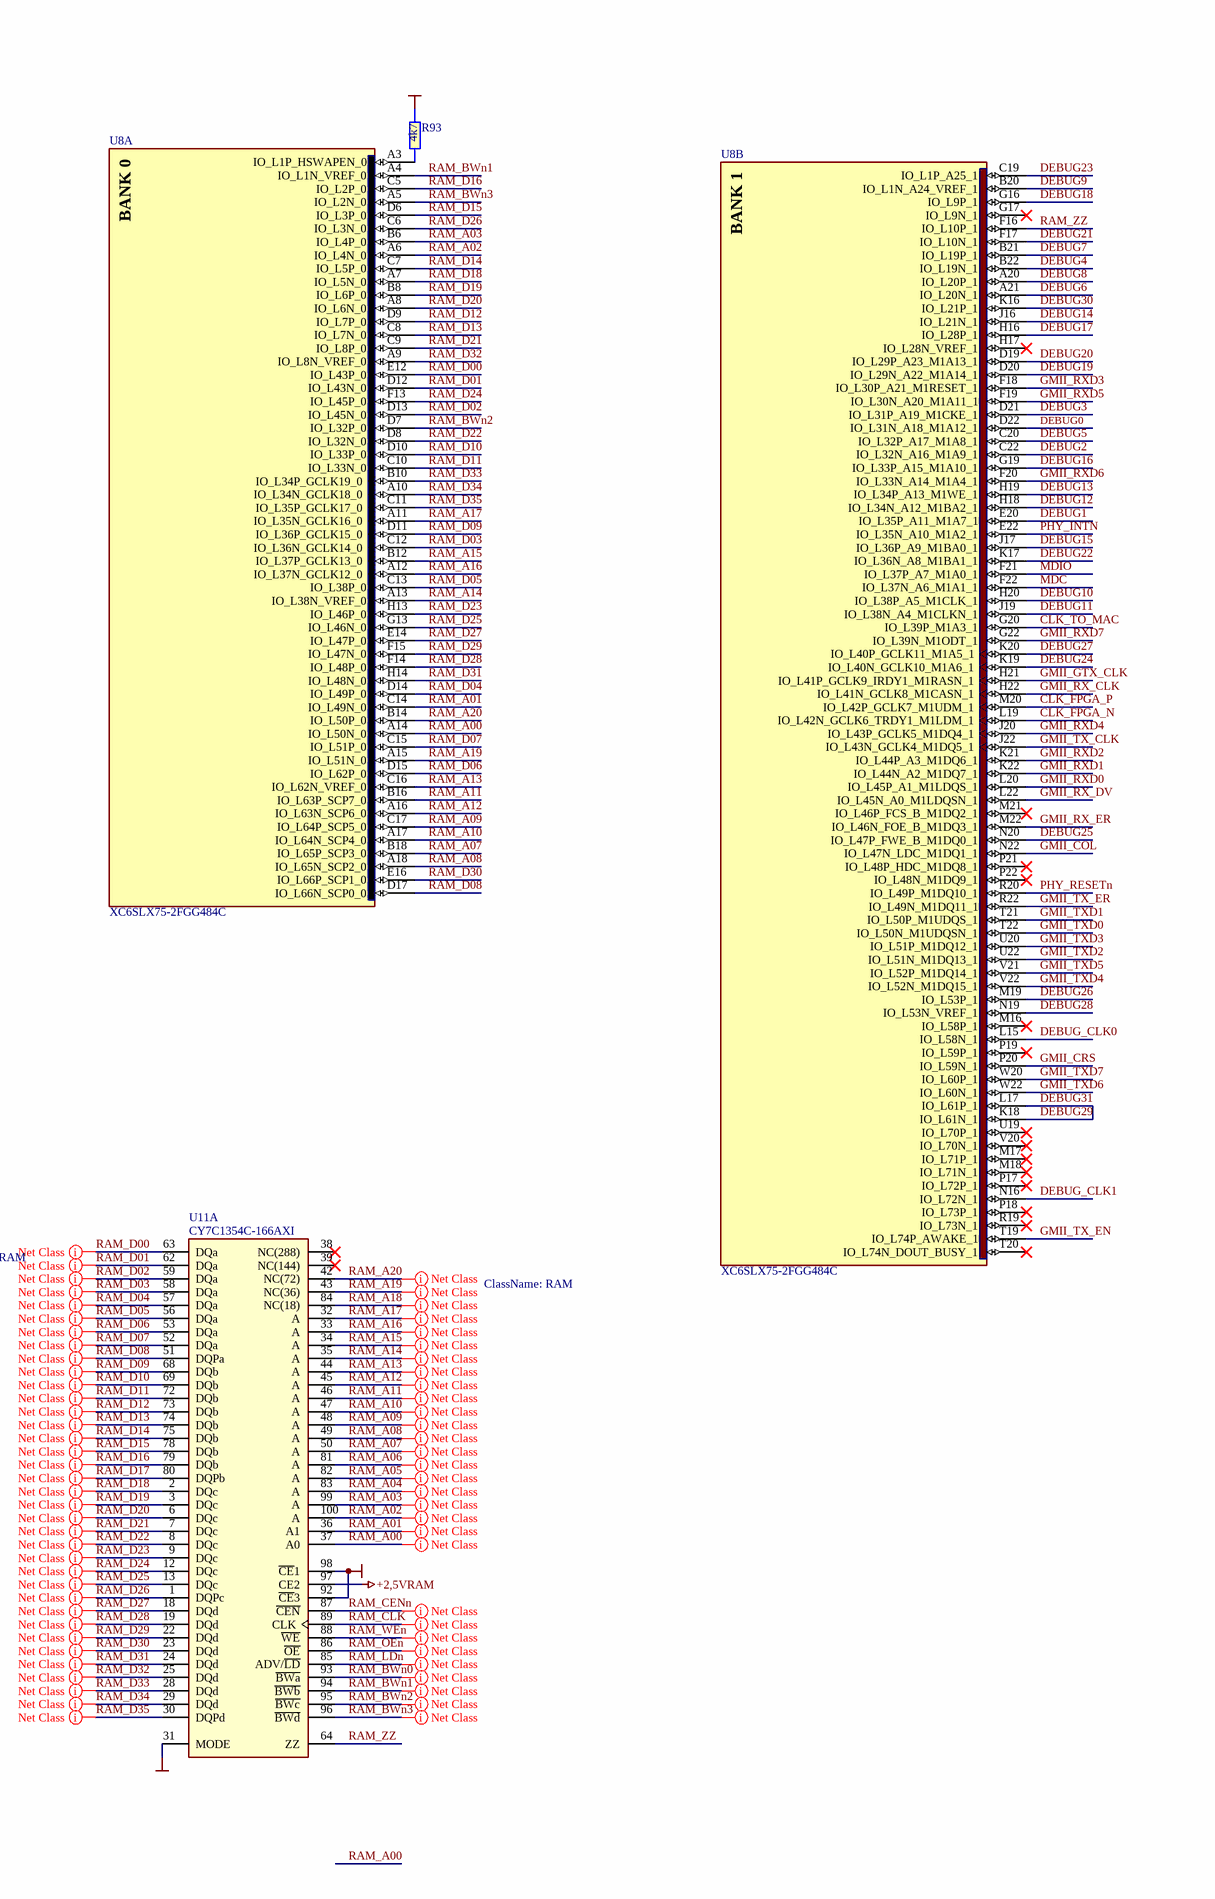
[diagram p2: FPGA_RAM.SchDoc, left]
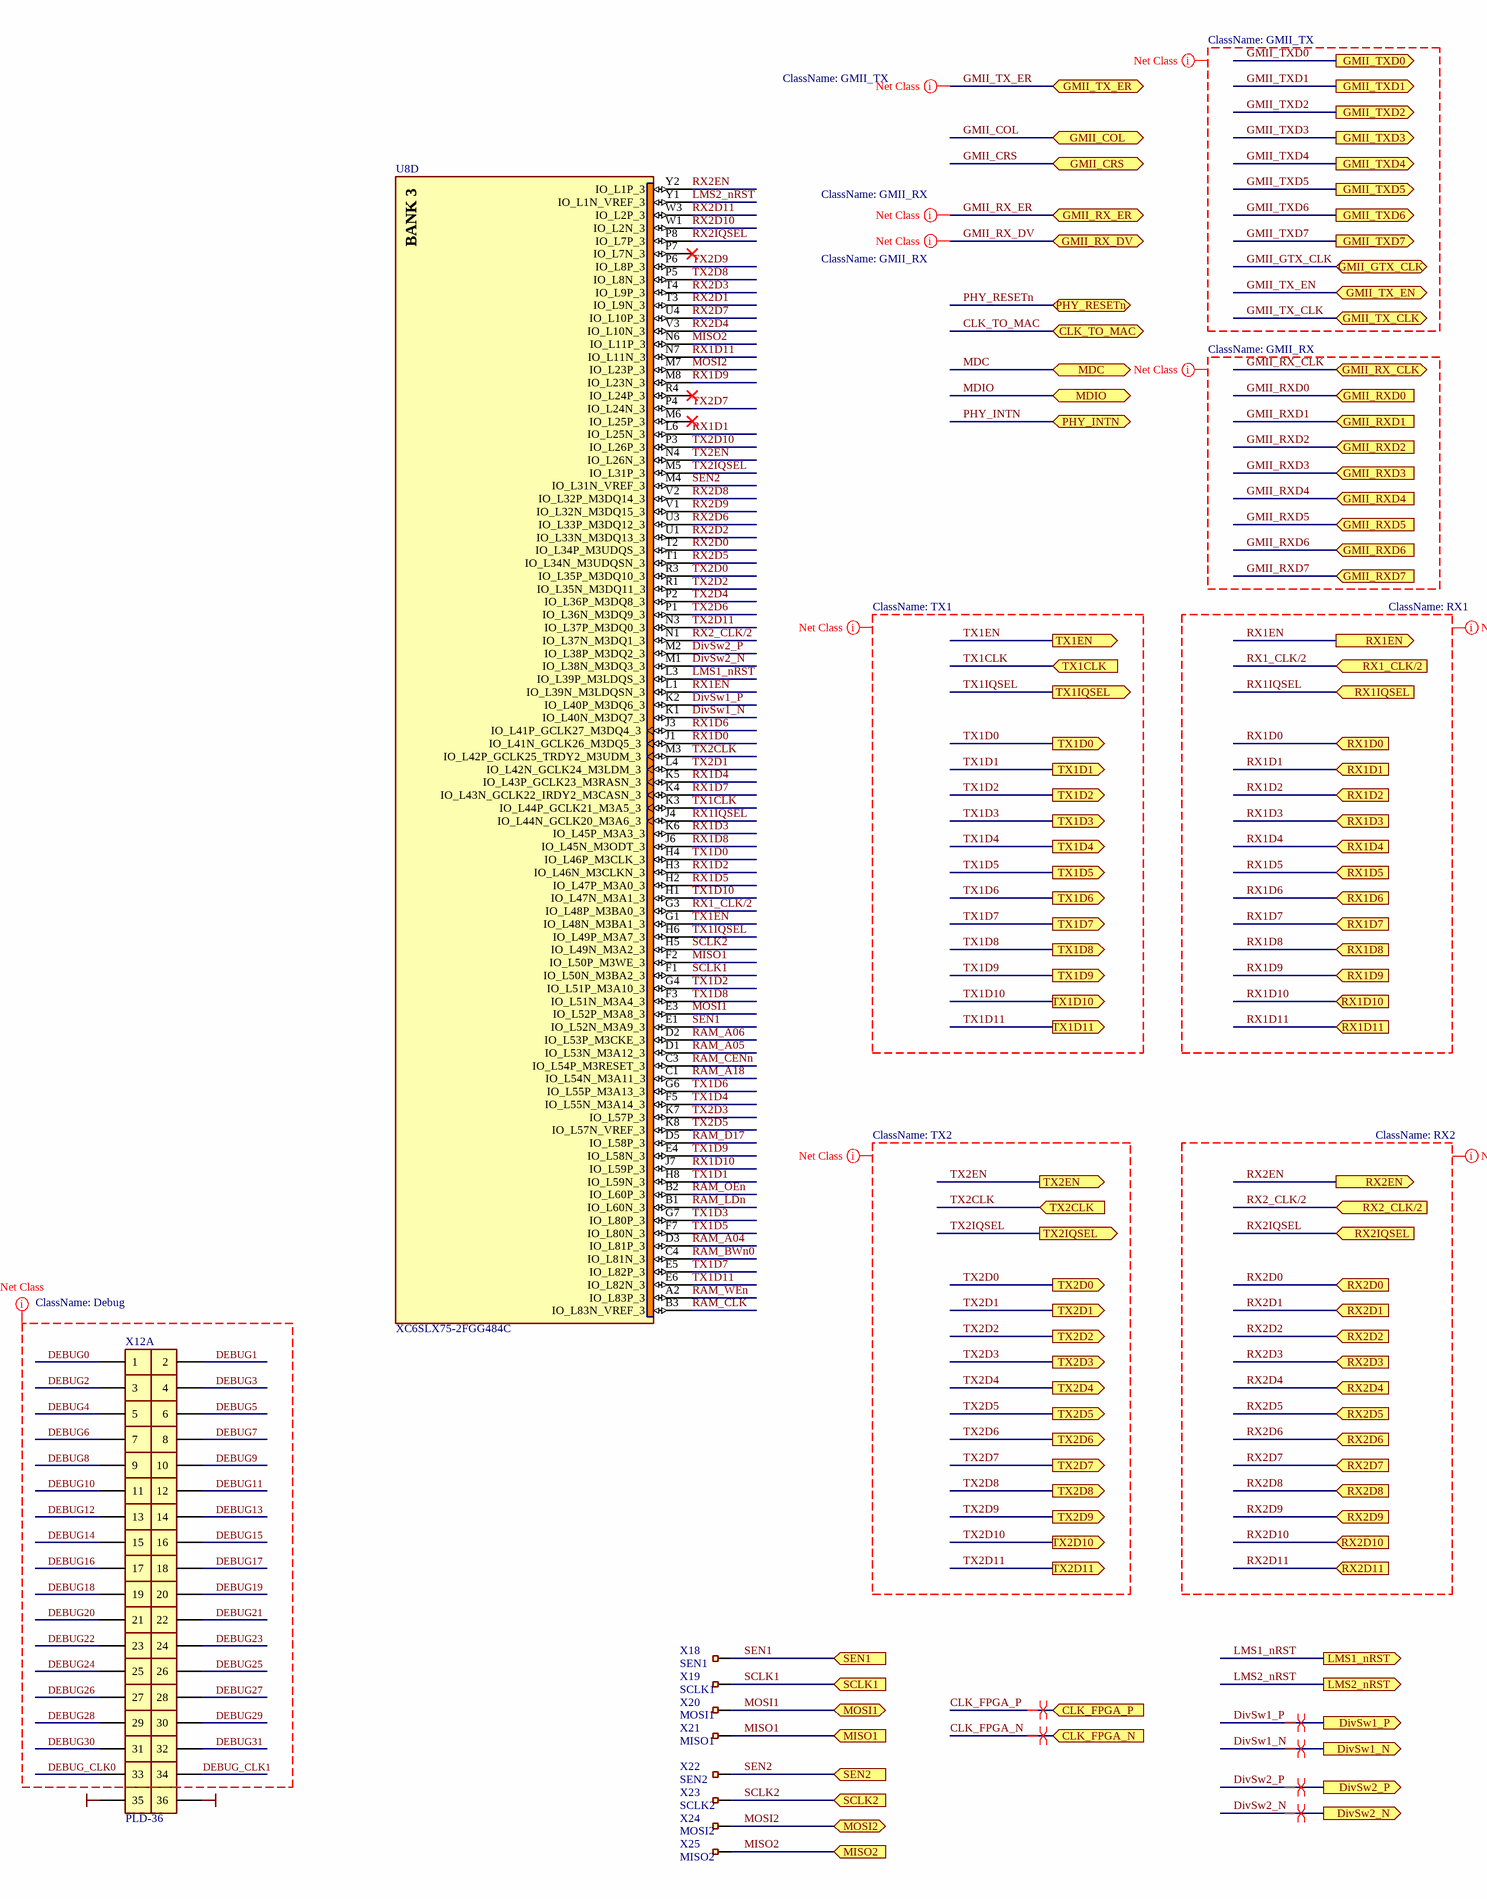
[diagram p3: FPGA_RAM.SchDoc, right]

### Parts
R93  4k7  [R0603-PHILLIPS]
U8  XC6SLX75-2FGG484C  [FBGA484]  (parts A,B,D of 8)
U11  CY7C1354C-166AXI  [QFP-10020X14/0.65]]  (part A of 2)
X12  PLD-36  [PLD-36]  (value not drawn)  (parts A,B,C,D,E,F,G,H,I,J,K,L,M,N,O,P,Q,R,S,T,U,V,W,X,Y,Z,27,28,29,30,31,32,33,34,35,36 of 36)
X18  SEN1  [kp40x40]
X19  SCLK1  [kp40x40]
X20  MOSI1  [kp40x40]
X21  MISO1  [kp40x40]
X22  SEN2  [kp40x40]
X23  SCLK2  [kp40x40]
X24  MOSI2  [kp40x40]
X25  MISO2  [kp40x40]

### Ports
CLK_FPGA_N (in), CLK_FPGA_P (in), CLK_TO_MAC, DivSw1_N (out), DivSw1_P (out), DivSw2_N (out), DivSw2_P (out), GMII_COL, GMII_CRS, GMII_GTX_CLK, GMII_RX_CLK, GMII_RX_DV, GMII_RX_ER, GMII_RXD0 (in), GMII_RXD1 (in), GMII_RXD2 (in), GMII_RXD3 (in), GMII_RXD4 (in), GMII_RXD5 (in), GMII_RXD6 (in), GMII_RXD7 (in), GMII_TX_CLK, GMII_TX_EN, GMII_TX_ER, GMII_TXD0 (out), GMII_TXD1 (out), GMII_TXD2 (out), GMII_TXD3 (out), GMII_TXD4 (out), GMII_TXD5 (out), GMII_TXD6 (out), GMII_TXD7 (out), LMS1_nRST (out), LMS2_nRST (out), MDC, MDIO, MISO1 (in), MISO2 (in), MOSI1 (bidir), MOSI2 (bidir), PHY_INTN, PHY_RESETn, RX1_CLK/2 (in), RX1D0 (in), RX1D1 (in), RX1D2 (in), RX1D3 (in), RX1D4 (in), RX1D5 (in), RX1D6 (in), RX1D7 (in), RX1D8 (in), RX1D9 (in), RX1D10 (in), RX1D11 (in), RX1EN (out), RX1IQSEL (in), RX2_CLK/2 (in), RX2D0 (in), RX2D1 (in), RX2D2 (in), RX2D3 (in), RX2D4 (in), RX2D5 (in), RX2D6 (in), RX2D7 (in), RX2D8 (in), RX2D9 (in), RX2D10 (in), RX2D11 (in), RX2EN (out), RX2IQSEL (in), SCLK1 (in), SCLK2 (in), SEN1 (in), SEN2 (in), TX1CLK (in), TX1D0 (out), TX1D1 (out), TX1D2 (out), TX1D3 (out), TX1D4 (out), TX1D5 (out), TX1D6 (out), TX1D7 (out), TX1D8 (out), TX1D9 (out), TX1D10 (out), TX1D11 (out), TX1EN (out), TX1IQSEL (out), TX2CLK (in), TX2D0 (out), TX2D1 (out), TX2D2 (out), TX2D3 (out), TX2D4 (out), TX2D5 (out), TX2D6 (out), TX2D7 (out), TX2D8 (out), TX2D9 (out), TX2D10 (out), TX2D11 (out), TX2EN (out), TX2IQSEL (out)

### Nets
+2,5VRAM: U11.97(CE2)
GND: R93.2 U11.31(MODE) U11.92(~{CE}3) U11.98(~{CE}1) X12.35 X12.36
CLK_FPGA_N: U8.L19(IO_L42N_GCLK6_TRDY1_M1LDM_1) ; port CLK_FPGA_N
CLK_FPGA_P: U8.M20(IO_L42P_GCLK7_M1UDM_1) ; port CLK_FPGA_P
CLK_TO_MAC: U8.G20(IO_L39P_M1A3_1) ; port CLK_TO_MAC
DEBUG0: U8.D22(IO_L31N_A18_M1A12_1) X12.1
DEBUG1: U8.E20(IO_L35P_A11_M1A7_1) X12.2
DEBUG2: U8.C22(IO_L32N_A16_M1A9_1) X12.3
DEBUG3: U8.D21(IO_L31P_A19_M1CKE_1) X12.4
DEBUG4: U8.B22(IO_L19N_1) X12.5
DEBUG5: U8.C20(IO_L32P_A17_M1A8_1) X12.6
DEBUG6: U8.A21(IO_L20N_1) X12.7
DEBUG7: U8.B21(IO_L19P_1) X12.8
DEBUG8: U8.A20(IO_L20P_1) X12.9
DEBUG9: U8.B20(IO_L1N_A24_VREF_1) X12.10
DEBUG10: U8.H20(IO_L38P_A5_M1CLK_1) X12.11
DEBUG11: U8.J19(IO_L38N_A4_M1CLKN_1) X12.12
DEBUG12: U8.H18(IO_L34N_A12_M1BA2_1) X12.13
DEBUG13: U8.H19(IO_L34P_A13_M1WE_1) X12.14
DEBUG14: U8.J16(IO_L21N_1) X12.15
DEBUG15: U8.J17(IO_L36P_A9_M1BA0_1) X12.16
DEBUG16: U8.G19(IO_L33P_A15_M1A10_1) X12.17
DEBUG17: U8.H16(IO_L28P_1) X12.18
DEBUG18: U8.G16(IO_L9P_1) X12.19
DEBUG19: U8.D20(IO_L29N_A22_M1A14_1) X12.20
DEBUG20: U8.D19(IO_L29P_A23_M1A13_1) X12.21
DEBUG21: U8.F17(IO_L10N_1) X12.22
DEBUG22: U8.K17(IO_L36N_A8_M1BA1_1) X12.23
DEBUG23: U8.C19(IO_L1P_A25_1) X12.24
DEBUG24: U8.K19(IO_L40N_GCLK10_M1A6_1) X12.25
DEBUG25: U8.N20(IO_L47P_FWE_B_M1DQ0_1) X12.26
DEBUG26: U8.M19(IO_L53P_1) X12.27
DEBUG27: U8.K20(IO_L40P_GCLK11_M1A5_1) X12.28
DEBUG28: U8.N19(IO_L53N_VREF_1) X12.29
DEBUG29: U8.K18(IO_L61N_1) U8.L17(IO_L61P_1) X12.30 X12.32  [also labelled DEBUG31]
DEBUG30: U8.K16(IO_L21P_1) X12.31
DEBUG_CLK0: U8.L15(IO_L58N_1) X12.33
DEBUG_CLK1: U8.N16(IO_L72N_1) X12.34
DivSw1_N: U8.K1(IO_L40N_M3DQ7_3) ; port DivSw1_N
DivSw1_P: U8.K2(IO_L40P_M3DQ6_3) ; port DivSw1_P
DivSw2_N: U8.M1(IO_L38N_M3DQ3_3) ; port DivSw2_N
DivSw2_P: U8.M2(IO_L38P_M3DQ2_3) ; port DivSw2_P
GMII_COL: U8.N22(IO_L47N_LDC_M1DQ1_1) ; port GMII_COL
GMII_CRS: U8.P20(IO_L59N_1) ; port GMII_CRS
GMII_GTX_CLK: U8.H21(IO_L41P_GCLK9_IRDY1_M1RASN_1) ; port GMII_GTX_CLK
GMII_RX_CLK: U8.H22(IO_L41N_GCLK8_M1CASN_1) ; port GMII_RX_CLK
GMII_RX_DV: U8.L22(IO_L45N_A0_M1LDQSN_1) ; port GMII_RX_DV
GMII_RX_ER: U8.M22(IO_L46N_FOE_B_M1DQ3_1) ; port GMII_RX_ER
GMII_RXD0: U8.L20(IO_L45P_A1_M1LDQS_1) ; port GMII_RXD0
GMII_RXD1: U8.K22(IO_L44N_A2_M1DQ7_1) ; port GMII_RXD1
GMII_RXD2: U8.K21(IO_L44P_A3_M1DQ6_1) ; port GMII_RXD2
GMII_RXD3: U8.F18(IO_L30P_A21_M1RESET_1) ; port GMII_RXD3
GMII_RXD4: U8.J20(IO_L43P_GCLK5_M1DQ4_1) ; port GMII_RXD4
GMII_RXD5: U8.F19(IO_L30N_A20_M1A11_1) ; port GMII_RXD5
GMII_RXD6: U8.F20(IO_L33N_A14_M1A4_1) ; port GMII_RXD6
GMII_RXD7: U8.G22(IO_L39N_M1ODT_1) ; port GMII_RXD7
GMII_TX_CLK: U8.J22(IO_L43N_GCLK4_M1DQ5_1) ; port GMII_TX_CLK
GMII_TX_EN: U8.T19(IO_L74P_AWAKE_1) ; port GMII_TX_EN
GMII_TX_ER: U8.R22(IO_L49N_M1DQ11_1) ; port GMII_TX_ER
GMII_TXD0: U8.T22(IO_L50N_M1UDQSN_1) ; port GMII_TXD0
GMII_TXD1: U8.T21(IO_L50P_M1UDQS_1) ; port GMII_TXD1
GMII_TXD2: U8.U22(IO_L51N_M1DQ13_1) ; port GMII_TXD2
GMII_TXD3: U8.U20(IO_L51P_M1DQ12_1) ; port GMII_TXD3
GMII_TXD4: U8.V22(IO_L52N_M1DQ15_1) ; port GMII_TXD4
GMII_TXD5: U8.V21(IO_L52P_M1DQ14_1) ; port GMII_TXD5
GMII_TXD6: U8.W22(IO_L60N_1) ; port GMII_TXD6
GMII_TXD7: U8.W20(IO_L60P_1) ; port GMII_TXD7
LMS1_nRST: U8.L3(IO_L39P_M3LDQS_3) ; port LMS1_nRST
LMS2_nRST: U8.Y1(IO_L1N_VREF_3) ; port LMS2_nRST
MDC: U8.F22(IO_L37N_A6_M1A1_1) ; port MDC
MDIO: U8.F21(IO_L37P_A7_M1A0_1) ; port MDIO
MISO1: U8.F2(IO_L50P_M3WE_3) X21.1 ; port MISO1
MISO2: U8.N6(IO_L11P_3) X25.1 ; port MISO2
MOSI1: U8.E3(IO_L52P_M3A8_3) X20.1 ; port MOSI1
MOSI2: U8.M7(IO_L23P_3) X24.1 ; port MOSI2
PHY_INTN: U8.E22(IO_L35N_A10_M1A2_1) ; port PHY_INTN
PHY_RESETn: U8.R20(IO_L49P_M1DQ10_1) ; port PHY_RESETn
RAM_A00: U8.A14(IO_L50N_0) U11.37(A0)
RAM_A01: U8.C14(IO_L49N_0) U11.36(A1)
RAM_A02: U8.A6(IO_L4N_0) U11.100(A)
RAM_A03: U8.B6(IO_L4P_0) U11.99(A)
RAM_A04: U8.D3(IO_L81P_3) U11.83(A)
RAM_A05: U8.D1(IO_L53N_M3A12_3) U11.82(A)
RAM_A06: U8.D2(IO_L53P_M3CKE_3) U11.81(A)
RAM_A07: U8.B18(IO_L65P_SCP3_0) U11.50(A)
RAM_A08: U8.A18(IO_L65N_SCP2_0) U11.49(A)
RAM_A09: U8.C17(IO_L64P_SCP5_0) U11.48(A)
RAM_A10: U8.A17(IO_L64N_SCP4_0) U11.47(A)
RAM_A11: U8.B16(IO_L63P_SCP7_0) U11.46(A)
RAM_A12: U8.A16(IO_L63N_SCP6_0) U11.45(A)
RAM_A13: U8.C16(IO_L62N_VREF_0) U11.44(A)
RAM_A14: U8.A13(IO_L38N_VREF_0) U11.35(A)
RAM_A15: U8.B12(IO_L37P_GCLK13_0) U11.34(A)
RAM_A16: U8.A12(IO_L37N_GCLK12_0) U11.33(A)
RAM_A17: U8.A11(IO_L35N_GCLK16_0) U11.32(A)
RAM_A18: U8.C1(IO_L54N_M3A11_3) U11.84(NC(18))
RAM_A19: U8.A15(IO_L51N_0) U11.43(NC(36))
RAM_A20: U8.B14(IO_L50P_0) U11.42(NC(72))
RAM_BWn0: U8.C4(IO_L81N_3) U11.93(~{BWa})
RAM_BWn1: U8.A4(IO_L1N_VREF_0) U11.94(~{BWb})
RAM_BWn2: U8.D7(IO_L32P_0) U11.95(~{BWc})
RAM_BWn3: U8.A5(IO_L2N_0) U11.96(~{BWd})
RAM_CENn: U8.C3(IO_L54P_M3RESET_3) U11.87(~{CEN})
RAM_CLK: U8.B3(IO_L83N_VREF_3) U11.89(CLK)
RAM_D00: U8.E12(IO_L43P_0) U11.63(DQa)
RAM_D01: U8.D12(IO_L43N_0) U11.62(DQa)
RAM_D02: U8.D13(IO_L45N_0) U11.59(DQa)
RAM_D03: U8.C12(IO_L36N_GCLK14_0) U11.58(DQa)
RAM_D04: U8.D14(IO_L49P_0) U11.57(DQa)
RAM_D05: U8.C13(IO_L38P_0) U11.56(DQa)
RAM_D06: U8.D15(IO_L62P_0) U11.53(DQa)
RAM_D07: U8.C15(IO_L51P_0) U11.52(DQa)
RAM_D08: U8.D17(IO_L66N_SCP0_0) U11.51(DQPa)
RAM_D09: U8.D11(IO_L36P_GCLK15_0) U11.68(DQb)
RAM_D10: U8.D10(IO_L33P_0) U11.69(DQb)
RAM_D11: U8.C10(IO_L33N_0) U11.72(DQb)
RAM_D12: U8.D9(IO_L7P_0) U11.73(DQb)
RAM_D13: U8.C8(IO_L7N_0) U11.74(DQb)
RAM_D14: U8.C7(IO_L5P_0) U11.75(DQb)
RAM_D15: U8.D6(IO_L3P_0) U11.78(DQb)
RAM_D16: U8.C5(IO_L2P_0) U11.79(DQb)
RAM_D17: U8.D5(IO_L58P_3) U11.80(DQPb)
RAM_D18: U8.A7(IO_L5N_0) U11.2(DQc)
RAM_D19: U8.B8(IO_L6P_0) U11.3(DQc)
RAM_D20: U8.A8(IO_L6N_0) U11.6(DQc)
RAM_D21: U8.C9(IO_L8P_0) U11.7(DQc)
RAM_D22: U8.D8(IO_L32N_0) U11.8(DQc)
RAM_D23: U8.H13(IO_L46P_0) U11.9(DQc)
RAM_D24: U8.F13(IO_L45P_0) U11.12(DQc)
RAM_D25: U8.G13(IO_L46N_0) U11.13(DQc)
RAM_D26: U8.C6(IO_L3N_0) U11.1(DQPc)
RAM_D27: U8.E14(IO_L47P_0) U11.18(DQd)
RAM_D28: U8.F14(IO_L48P_0) U11.19(DQd)
RAM_D29: U8.F15(IO_L47N_0) U11.22(DQd)
RAM_D30: U8.E16(IO_L66P_SCP1_0) U11.23(DQd)
RAM_D31: U8.H14(IO_L48N_0) U11.24(DQd)
RAM_D32: U8.A9(IO_L8N_VREF_0) U11.25(DQd)
RAM_D33: U8.B10(IO_L34P_GCLK19_0) U11.28(DQd)
RAM_D34: U8.A10(IO_L34N_GCLK18_0) U11.29(DQd)
RAM_D35: U8.C11(IO_L35P_GCLK17_0) U11.30(DQPd)
RAM_LDn: U8.B1(IO_L60N_3) U11.85(ADV/~{LD})
RAM_OEn: U8.B2(IO_L60P_3) U11.86(~{OE})
RAM_WEn: U8.A2(IO_L83P_3) U11.88(~{WE})
RAM_ZZ: U8.F16(IO_L10P_1) U11.64(ZZ)
RX1_CLK/2: U8.G3(IO_L48P_M3BA0_3) ; port RX1_CLK/2
RX1D0: U8.J1(IO_L41N_GCLK26_M3DQ5_3) ; port RX1D0
RX1D1: U8.L6(IO_L25N_3) ; port RX1D1
RX1D2: U8.H3(IO_L46N_M3CLKN_3) ; port RX1D2
RX1D3: U8.K6(IO_L45P_M3A3_3) ; port RX1D3
RX1D4: U8.K5(IO_L43P_GCLK23_M3RASN_3) ; port RX1D4
RX1D5: U8.H2(IO_L47P_M3A0_3) ; port RX1D5
RX1D6: U8.J3(IO_L41P_GCLK27_M3DQ4_3) ; port RX1D6
RX1D7: U8.K4(IO_L43N_GCLK22_IRDY2_M3CASN_3) ; port RX1D7
RX1D8: U8.J6(IO_L45N_M3ODT_3) ; port RX1D8
RX1D9: U8.M8(IO_L23N_3) ; port RX1D9
RX1D10: U8.J7(IO_L59P_3) ; port RX1D10
RX1D11: U8.N7(IO_L11N_3) ; port RX1D11
RX1EN: U8.L1(IO_L39N_M3LDQSN_3) ; port RX1EN
RX1IQSEL: U8.J4(IO_L44N_GCLK20_M3A6_3) ; port RX1IQSEL
RX2_CLK/2: U8.N1(IO_L37N_M3DQ1_3) ; port RX2_CLK/2
RX2D0: U8.T2(IO_L34P_M3UDQS_3) ; port RX2D0
RX2D1: U8.T3(IO_L9N_3) ; port RX2D1
RX2D2: U8.U1(IO_L33N_M3DQ13_3) ; port RX2D2
RX2D3: U8.T4(IO_L9P_3) ; port RX2D3
RX2D4: U8.V3(IO_L10N_3) ; port RX2D4
RX2D5: U8.T1(IO_L34N_M3UDQSN_3) ; port RX2D5
RX2D6: U8.U3(IO_L33P_M3DQ12_3) ; port RX2D6
RX2D7: U8.U4(IO_L10P_3) ; port RX2D7
RX2D8: U8.V2(IO_L32P_M3DQ14_3) ; port RX2D8
RX2D9: U8.V1(IO_L32N_M3DQ15_3) ; port RX2D9
RX2D10: U8.W1(IO_L2N_3) ; port RX2D10
RX2D11: U8.W3(IO_L2P_3) ; port RX2D11
RX2EN: U8.Y2(IO_L1P_3) ; port RX2EN
RX2IQSEL: U8.P8(IO_L7P_3) ; port RX2IQSEL
SCLK1: U8.F1(IO_L50N_M3BA2_3) X19.1 ; port SCLK1
SCLK2: U8.H5(IO_L49N_M3A2_3) X23.1 ; port SCLK2
SEN1: U8.E1(IO_L52N_M3A9_3) X18.1 ; port SEN1
SEN2: U8.M4(IO_L31N_VREF_3) X22.1 ; port SEN2
TX1CLK: U8.K3(IO_L44P_GCLK21_M3A5_3) ; port TX1CLK
TX1D0: U8.H4(IO_L46P_M3CLK_3) ; port TX1D0
TX1D1: U8.H8(IO_L59N_3) ; port TX1D1
TX1D2: U8.G4(IO_L51P_M3A10_3) ; port TX1D2
TX1D3: U8.G7(IO_L80P_3) ; port TX1D3
TX1D4: U8.F5(IO_L55N_M3A14_3) ; port TX1D4
TX1D5: U8.F7(IO_L80N_3) ; port TX1D5
TX1D6: U8.G6(IO_L55P_M3A13_3) ; port TX1D6
TX1D7: U8.E5(IO_L82P_3) ; port TX1D7
TX1D8: U8.F3(IO_L51N_M3A4_3) ; port TX1D8
TX1D9: U8.E4(IO_L58N_3) ; port TX1D9
TX1D10: U8.H1(IO_L47N_M3A1_3) ; port TX1D10
TX1D11: U8.E6(IO_L82N_3) ; port TX1D11
TX1EN: U8.G1(IO_L48N_M3BA1_3) ; port TX1EN
TX1IQSEL: U8.H6(IO_L49P_M3A7_3) ; port TX1IQSEL
TX2CLK: U8.M3(IO_L42P_GCLK25_TRDY2_M3UDM_3) ; port TX2CLK
TX2D0: U8.R3(IO_L35P_M3DQ10_3) ; port TX2D0
TX2D1: U8.L4(IO_L42N_GCLK24_M3LDM_3) ; port TX2D1
TX2D2: U8.R1(IO_L35N_M3DQ11_3) ; port TX2D2
TX2D3: U8.K7(IO_L57P_3) ; port TX2D3
TX2D4: U8.P2(IO_L36P_M3DQ8_3) ; port TX2D4
TX2D5: U8.K8(IO_L57N_VREF_3) ; port TX2D5
TX2D6: U8.P1(IO_L36N_M3DQ9_3) ; port TX2D6
TX2D7: U8.P4(IO_L24N_3) ; port TX2D7
TX2D8: U8.P5(IO_L8N_3) ; port TX2D8
TX2D9: U8.P6(IO_L8P_3) ; port TX2D9
TX2D10: U8.P3(IO_L26P_3) ; port TX2D10
TX2D11: U8.N3(IO_L37P_M3DQ0_3) ; port TX2D11
TX2EN: U8.N4(IO_L26N_3) ; port TX2EN
TX2IQSEL: U8.M5(IO_L31P_3) ; port TX2IQSEL
NetR93_1: R93.1 U8.A3(IO_L1P_HSWAPEN_0)

Not connected (* = marked no-connect by the designer): U8 G17(IO_L9N_1)* H17(IO_L28N_VREF_1)* M6(IO_L25P_3)* M16(IO_L58P_1)* M17(IO_L71P_1)* M18(IO_L71N_1)* M21(IO_L46P_FCS_B_M1DQ2_1)* P7(IO_L7N_3)* P17(IO_L72P_1)* P18(IO_L73P_1)* P19(IO_L59P_1)* P21(IO_L48P_HDC_M1DQ8_1)* P22(IO_L48N_M1DQ9_1)* R4(IO_L24P_3)* R19(IO_L73N_1)* T20(IO_L74N_DOUT_BUSY_1)* U19(IO_L70P_1)* V20(IO_L70N_1)*; U11 38(NC(288))* 39(NC(144))*

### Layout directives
net class RX1: RX1_CLK/2, RX1D0, RX1D1, RX1D2, RX1D3, RX1D4, RX1D5, RX1D6, RX1D7, RX1D8, RX1D9, RX1D10, RX1D11, RX1EN, RX1IQSEL
net class RX2: RX2_CLK/2, RX2D0, RX2D1, RX2D2, RX2D3, RX2D4, RX2D5, RX2D6, RX2D7, RX2D8, RX2D9, RX2D10, RX2D11, RX2EN, RX2IQSEL
net class TX1: TX1CLK, TX1D0, TX1D1, TX1D2, TX1D3, TX1D4, TX1D5, TX1D6, TX1D7, TX1D8, TX1D9, TX1D10, TX1D11, TX1EN, TX1IQSEL
net class TX2: TX2CLK, TX2D0, TX2D1, TX2D2, TX2D3, TX2D4, TX2D5, TX2D6, TX2D7, TX2D8, TX2D9, TX2D10, TX2D11, TX2EN, TX2IQSEL
net class GMII_TX: GMII_GTX_CLK, GMII_TX_CLK, GMII_TX_EN, GMII_TX_ER, GMII_TXD0, GMII_TXD1, GMII_TXD2, GMII_TXD3, GMII_TXD4, GMII_TXD5, GMII_TXD6, GMII_TXD7
net class RAM: RAM_A00, RAM_A01, RAM_A02, RAM_A03, RAM_A04, RAM_A05, RAM_A06, RAM_A07, RAM_A08, RAM_A09, RAM_A10, RAM_A11, RAM_A12, RAM_A13, RAM_A14, RAM_A15, RAM_A16, RAM_A17, RAM_A18, RAM_A19, RAM_A20, RAM_BWn0, RAM_BWn1, RAM_BWn2, RAM_BWn3, RAM_CENn, RAM_CLK, RAM_D00, RAM_D01, RAM_D02, RAM_D03, RAM_D04, RAM_D05, RAM_D06, RAM_D07, RAM_D08, RAM_D09, RAM_D10, RAM_D11, RAM_D12, RAM_D13, RAM_D14, RAM_D15, RAM_D16, RAM_D17, RAM_D18, RAM_D19, RAM_D20, RAM_D21, RAM_D22, RAM_D23, RAM_D24, RAM_D25, RAM_D26, RAM_D27, RAM_D28, RAM_D29, RAM_D30, RAM_D31, RAM_D32, RAM_D33, RAM_D34, RAM_D35, RAM_LDn, RAM_OEn, RAM_WEn
differential pair: CLK_FPGA_N, CLK_FPGA_P, DivSw1_N, DivSw1_P, DivSw2_N, DivSw2_P
net class GMII_RX: GMII_RX_CLK, GMII_RX_DV, GMII_RX_ER, GMII_RXD0, GMII_RXD1, GMII_RXD2, GMII_RXD3, GMII_RXD4, GMII_RXD5, GMII_RXD6, GMII_RXD7
net class Debug: DEBUG0, DEBUG1, DEBUG2, DEBUG3, DEBUG4, DEBUG5, DEBUG6, DEBUG7, DEBUG8, DEBUG9, DEBUG10, DEBUG11, DEBUG12, DEBUG13, DEBUG14, DEBUG15, DEBUG16, DEBUG17, DEBUG18, DEBUG19, DEBUG20, DEBUG21, DEBUG22, DEBUG23, DEBUG24, DEBUG25, DEBUG26, DEBUG27, DEBUG28, DEBUG29, DEBUG30, DEBUG31, DEBUG_CLK0, DEBUG_CLK1

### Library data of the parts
R93 = R0603: as R128 on sheet PwrAndBias
U8 = XC6SLX75-2FGG484C: as U8 on sheet PwrAndBias
U11 = CY7C1354C-166AXI: as U11 on sheet PwrAndBias
X12 = PLD-36: Разъем; Manufacturer: BM
X18-X25 = KP: Контактная площадка; Manufacturer: Конструктив

## Sheet GBEthernet.SchDoc: BaseBand Front-End
size A3; Revision: 1; SheetNumber: 6
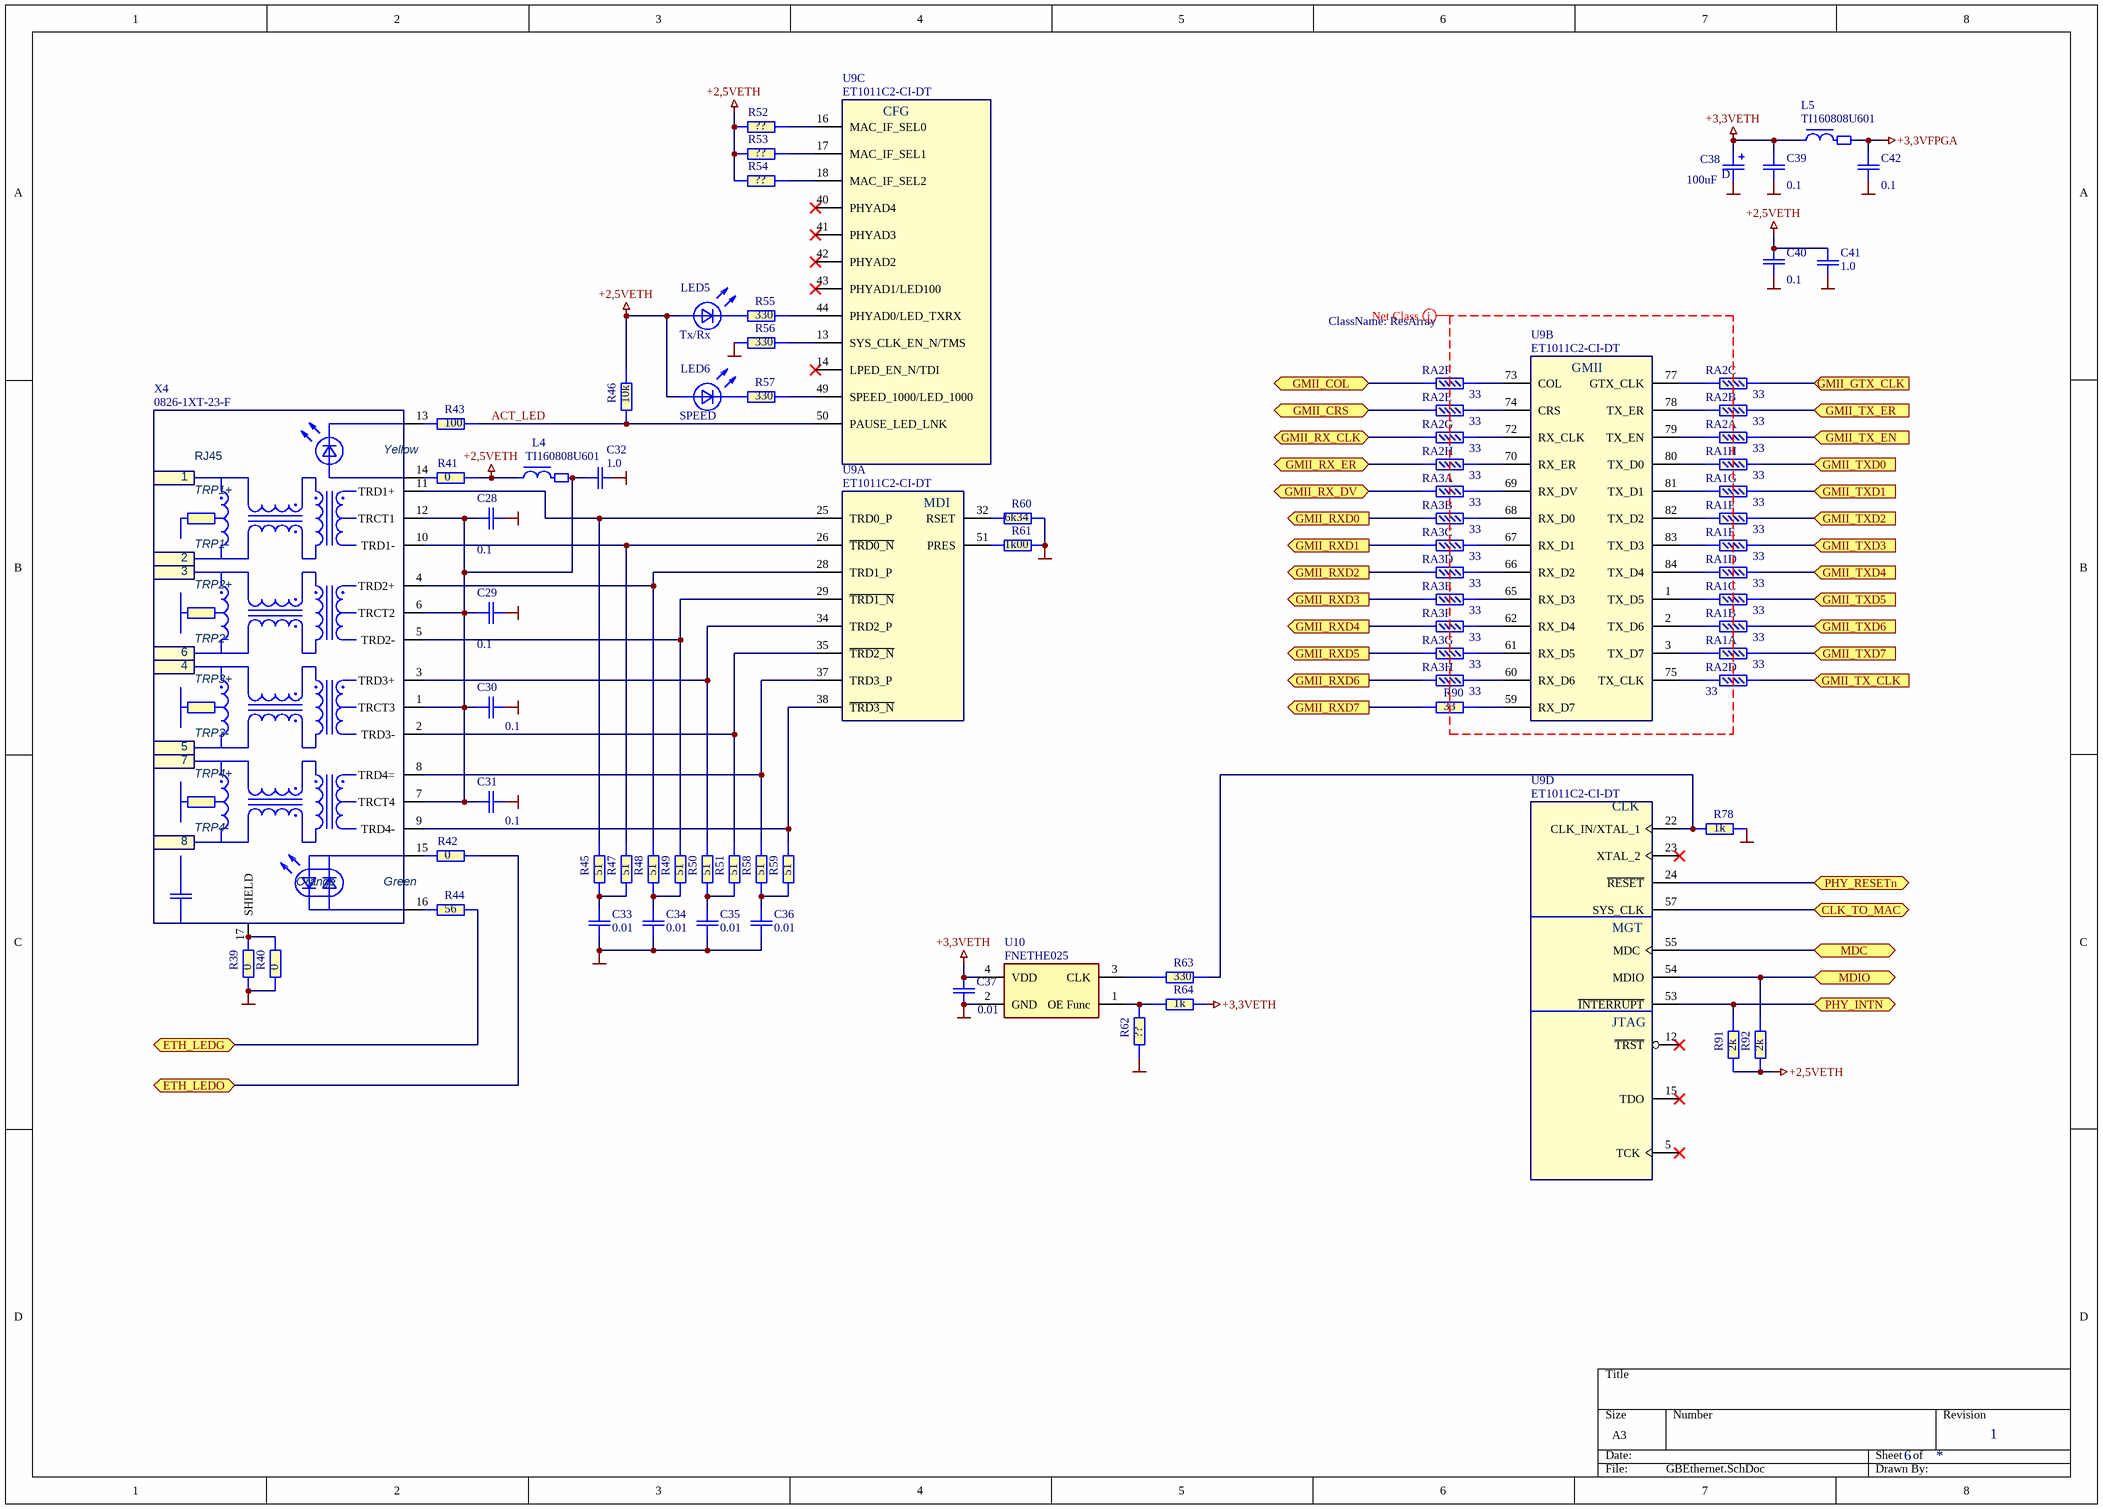
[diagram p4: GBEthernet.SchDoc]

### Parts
C28  0.1  [C0402-Phillips]
C29  0.1  [C0402-Phillips]
C30  0.1  [C0402-Phillips]
C31  0.1  [C0402-Phillips]
C32  1.0  [C0603-PHILLIPS]
C33  0.01  [C0402-Phillips]
C34  0.01  [C0402-Phillips]
C35  0.01  [C0402-Phillips]
C36  0.01  [C0402-Phillips]
C37  0.01  [C0402-Phillips]
C38  100uF  [cd7343]
C39  0.1  [C0402-Phillips]
C40  0.1  [C0402-Phillips]
C41  1.0  [C0603-PHILLIPS]
C42  0.1  [C0402-Phillips]
L4  TI160808U601  [Ti160808-Phillips]
L5  TI160808U601  [Ti160808-Phillips]
LED5  Tx/Rx  [LED-0603y]
LED6  SPEED  [LED-0603y]
R39  0  [R0603-PHILLIPS]
R40  0  [R0603-PHILLIPS]
R41  0  [R0603-PHILLIPS]
R42  0  [R0603-PHILLIPS]
R43  100  [R0603-PHILLIPS]
R44  56  [R0603-PHILLIPS]
R45  51  [R0603-PHILLIPS]
R46  10k  [R0603-PHILLIPS]
R47  51  [R0603-PHILLIPS]
R48  51  [R0603-PHILLIPS]
R49  51  [R0603-PHILLIPS]
R50  51  [R0603-PHILLIPS]
R51  51  [R0603-PHILLIPS]
R52  ??  [R0603-PHILLIPS]
R53  ??  [R0603-PHILLIPS]
R54  ??  [R0603-PHILLIPS]
R55  330  [R0603-PHILLIPS]
R56  330  [R0603-PHILLIPS]
R57  330  [R0603-PHILLIPS]
R58  51  [R0603-PHILLIPS]
R59  51  [R0603-PHILLIPS]
R60  6k34  [R0603-PHILLIPS]
R61  1k00  [R0603-PHILLIPS]
R62  ??  [R0603-PHILLIPS]
R63  330  [R0603-PHILLIPS]
R64  1k  [R0603-PHILLIPS]
R78  1k  [R0603-PHILLIPS]
R90  33  [R0603-PHILLIPS]
R91  2k  [R0603-PHILLIPS]
R92  2k  [R0603-PHILLIPS]
RA1  33  [YC248]  (parts A,B,C,D,E,F,G,H of 8)
RA2  33  [YC248]  (parts A,B,C,D,E,F,G,H of 8)
RA3  33  [YC248]  (parts A,B,C,D,E,F,G,H of 8)
U9  ET1011C2-CI-DT  [QFN-84(10x10/0/4mm)with_pad]  (parts A,B,C,D of 5)
U10  FNETHE025  [7x5mm]
X4  0826-1XT-23-F  [Bel0826-1XT-23F]

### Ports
CLK_TO_MAC, ETH_LEDG, ETH_LEDO, GMII_COL, GMII_CRS, GMII_GTX_CLK (in), GMII_RX_CLK, GMII_RX_DV, GMII_RX_ER, GMII_RXD0 (out), GMII_RXD1 (out), GMII_RXD2 (out), GMII_RXD3 (out), GMII_RXD4 (out), GMII_RXD5 (out), GMII_RXD6 (out), GMII_RXD7 (out), GMII_TX_CLK (in), GMII_TX_EN (in), GMII_TX_ER (in), GMII_TXD0 (in), GMII_TXD1 (in), GMII_TXD2 (in), GMII_TXD3 (in), GMII_TXD4 (in), GMII_TXD5 (in), GMII_TXD6 (in), GMII_TXD7 (in), MDC, MDIO, PHY_INTN, PHY_RESETn

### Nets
+2,5VETH: C40.1 C41.2 L4.1 LED5.2(A) LED6.2(A) R41.2 R46.2 R52.1 R53.1 R54.1 R91.1 R92.1
+3,3VETH: C37.1 C38.1(+) C39.1 L5.1 R64.2 U10.4(VDD)
+3,3VFPGA: C42.1 L5.2
GND: C28.2 C29.2 C30.2 C31.2 C32.1 C33.2 C34.2 C35.2 C36.2 C37.2 C38.2(-) C39.2 C40.2 C41.1 C42.2 R39.1 R40.1 R56.1 R60.2 R61.2 R62.1 R78.2 U10.2(GND)
ACT_LED: R43.2 R46.1 U9.50(PAUSE_LED_LNK)
CLK_TO_MAC: U9.57(SYS_CLK) ; port CLK_TO_MAC
ETH_LEDG: R44.2 ; port ETH_LEDG
ETH_LEDO: R42.2 ; port ETH_LEDO
GMII_COL: RA2.11 ; port GMII_COL
GMII_CRS: RA2.12 ; port GMII_CRS
GMII_GTX_CLK: RA2.14 ; port GMII_GTX_CLK
GMII_RX_CLK: RA2.10 ; port GMII_RX_CLK
GMII_RX_DV: RA3.16 ; port GMII_RX_DV
GMII_RX_ER: RA2.9 ; port GMII_RX_ER
GMII_RXD0: RA3.15 ; port GMII_RXD0
GMII_RXD1: RA3.14 ; port GMII_RXD1
GMII_RXD2: RA3.13 ; port GMII_RXD2
GMII_RXD3: RA3.12 ; port GMII_RXD3
GMII_RXD4: RA3.11 ; port GMII_RXD4
GMII_RXD5: RA3.10 ; port GMII_RXD5
GMII_RXD6: RA3.9 ; port GMII_RXD6
GMII_RXD7: R90.1 ; port GMII_RXD7
GMII_TX_CLK: RA2.13 ; port GMII_TX_CLK
GMII_TX_EN: RA2.16 ; port GMII_TX_EN
GMII_TX_ER: RA2.15 ; port GMII_TX_ER
GMII_TXD0: RA1.9 ; port GMII_TXD0
GMII_TXD1: RA1.10 ; port GMII_TXD1
GMII_TXD2: RA1.11 ; port GMII_TXD2
GMII_TXD3: RA1.12 ; port GMII_TXD3
GMII_TXD4: RA1.13 ; port GMII_TXD4
GMII_TXD5: RA1.14 ; port GMII_TXD5
GMII_TXD6: RA1.15 ; port GMII_TXD6
GMII_TXD7: RA1.16 ; port GMII_TXD7
MDC: U9.55(MDC) ; port MDC
MDIO: R92.2 U9.54(MDIO) ; port MDIO
PHY_INTN: R91.2 U9.53(~{INTERRUPT}) ; port PHY_INTN
PHY_RESETn: U9.24(~{RESET}) ; port PHY_RESETn
NetC28_1: C28.1 C29.1 C30.1 C31.1 C32.2 L4.2 X4.1(TRCT3) X4.6(TRCT2) X4.7(TRCT4) X4.12(TRCT1)
NetC33_1: C33.1 R45.1 R47.1
NetC34_1: C34.1 R48.1 R49.1
NetC35_1: C35.1 R50.1 R51.1
NetC36_1: C36.1 R58.1 R59.1
NetLED5_1: LED5.1(K) R55.1
NetLED6_1: LED6.1(K) R57.1
NetR39_2: R39.2 R40.2 X4.17(SHIELD)
NetR41_1: R41.1 X4.14(LED1+)
NetR42_1: R42.1 X4.15(LED2-O)
NetR43_1: R43.1 X4.13(LED1-)
NetR44_1: R44.1 X4.16(LED2-G)
NetR45_2: R45.2 U9.25(TRD0_P) X4.11(TRD1+)
NetR47_2: R47.2 U9.26(~{TRD0_N}) X4.10(TRD1-)
NetR48_2: R48.2 U9.28(TRD1_P) X4.4(TRD2+)
NetR49_2: R49.2 U9.29(~{TRD1_N}) X4.5(TRD2-)
NetR50_2: R50.2 U9.34(TRD2_P) X4.3(TRD3+)
NetR51_2: R51.2 U9.35(~{TRD2_N}) X4.2(TRD3-)
NetR52_2: R52.2 U9.16(MAC_IF_SEL0)
NetR53_2: R53.2 U9.17(MAC_IF_SEL1)
NetR54_2: R54.2 U9.18(MAC_IF_SEL2)
NetR55_2: R55.2 U9.44(PHYAD0/LED_TXRX)
NetR56_2: R56.2 U9.13(SYS_CLK_EN_N/TMS)
NetR57_2: R57.2 U9.49(SPEED_1000/LED_1000)
NetR58_2: R58.2 U9.37(TRD3_P) X4.8(TRD4=)
NetR59_2: R59.2 U9.38(~{TRD3_N}) X4.9(TRD4-)
NetR60_1: R60.1 U9.32(RSET)
NetR61_1: R61.1 U9.51(PRES)
NetR62_2: R62.2 R64.1 U10.1(OE_Func)
NetR63_1: R63.1 U10.3(CLK)
NetR63_2: R63.2 R78.1 U9.22(CLK_IN/XTAL_1)
NetR90_2: R90.2 U9.59(RX_D7)
NetRA1_1: RA1.1 U9.3(TX_D7)
NetRA1_2: RA1.2 U9.2(TX_D6)
NetRA1_3: RA1.3 U9.1(TX_D5)
NetRA1_4: RA1.4 U9.84(TX_D4)
NetRA1_5: RA1.5 U9.83(TX_D3)
NetRA1_6: RA1.6 U9.82(TX_D2)
NetRA1_7: RA1.7 U9.81(TX_D1)
NetRA1_8: RA1.8 U9.80(TX_D0)
NetRA2_1: RA2.1 U9.79(TX_EN)
NetRA2_2: RA2.2 U9.78(TX_ER)
NetRA2_3: RA2.3 U9.77(GTX_CLK)
NetRA2_4: RA2.4 U9.75(TX_CLK)
NetRA2_5: RA2.5 U9.74(CRS)
NetRA2_6: RA2.6 U9.73(COL)
NetRA2_7: RA2.7 U9.72(RX_CLK)
NetRA2_8: RA2.8 U9.70(RX_ER)
NetRA3_1: RA3.1 U9.69(RX_DV)
NetRA3_2: RA3.2 U9.68(RX_D0)
NetRA3_3: RA3.3 U9.67(RX_D1)
NetRA3_4: RA3.4 U9.66(RX_D2)
NetRA3_5: RA3.5 U9.65(RX_D3)
NetRA3_6: RA3.6 U9.62(RX_D4)
NetRA3_7: RA3.7 U9.61(RX_D5)
NetRA3_8: RA3.8 U9.60(RX_D6)

Not connected (* = marked no-connect by the designer): U9 5(TCK)* 12(~{TRST})* 14(LPED_EN_N/TDI)* 15(TDO)* 23(XTAL_2)* 40(PHYAD4)* 41(PHYAD3)* 42(PHYAD2)* 43(PHYAD1/LED100)*

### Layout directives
net class ResArray: (no net found under the mark)

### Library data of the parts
C28-C31 C33-C37 C39 C40 C42 = C0402: as C113 on sheet PwrAndBias
C32 C41 = C0603: as C170 on sheet PwrAndBias
C38 = CD7343: as C125 on sheet PwrAndBias
L4 L5 = TI160808: Дроссель ЭМС; Manufacturer: MURATA
LED5 LED6 = LED0603: Светодиод
R39-R59 R62-R64 R78 R90-R92 = R0603: as R128 on sheet PwrAndBias
R60 R61 = R0603: Резистор; Manufacturer: YAGEO; Tolerance: 1%; Name: SMD0603; U/P/TKE: 0.1W
RA1-RA3 = YC248: Резисторная сборка; Manufacturer: Yageo; Misc: Резисторная сборка 8 шт. шаг 0.5 мм; U/P/TKE: 0.062W; Tolerance: 5%
U9 = ET1011C2-CI-DT: as U9 on sheet PwrAndBias
U10 = FNETHE025: Генератор; Manufacturer: Saronix-eCera; Swap: No; PDF: d:\Proj\Components\Разное\FNETHE025.pdf; Misc: Low-Jitter 25MHz Gbe XO
X4 = RJ45 0826-1XT-23-F: Модуль разъёма; Manufacturer: Bel Fuse; PDF: d:\Proj\Components\Разъемы\0826-1X1T-23-F.pdf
